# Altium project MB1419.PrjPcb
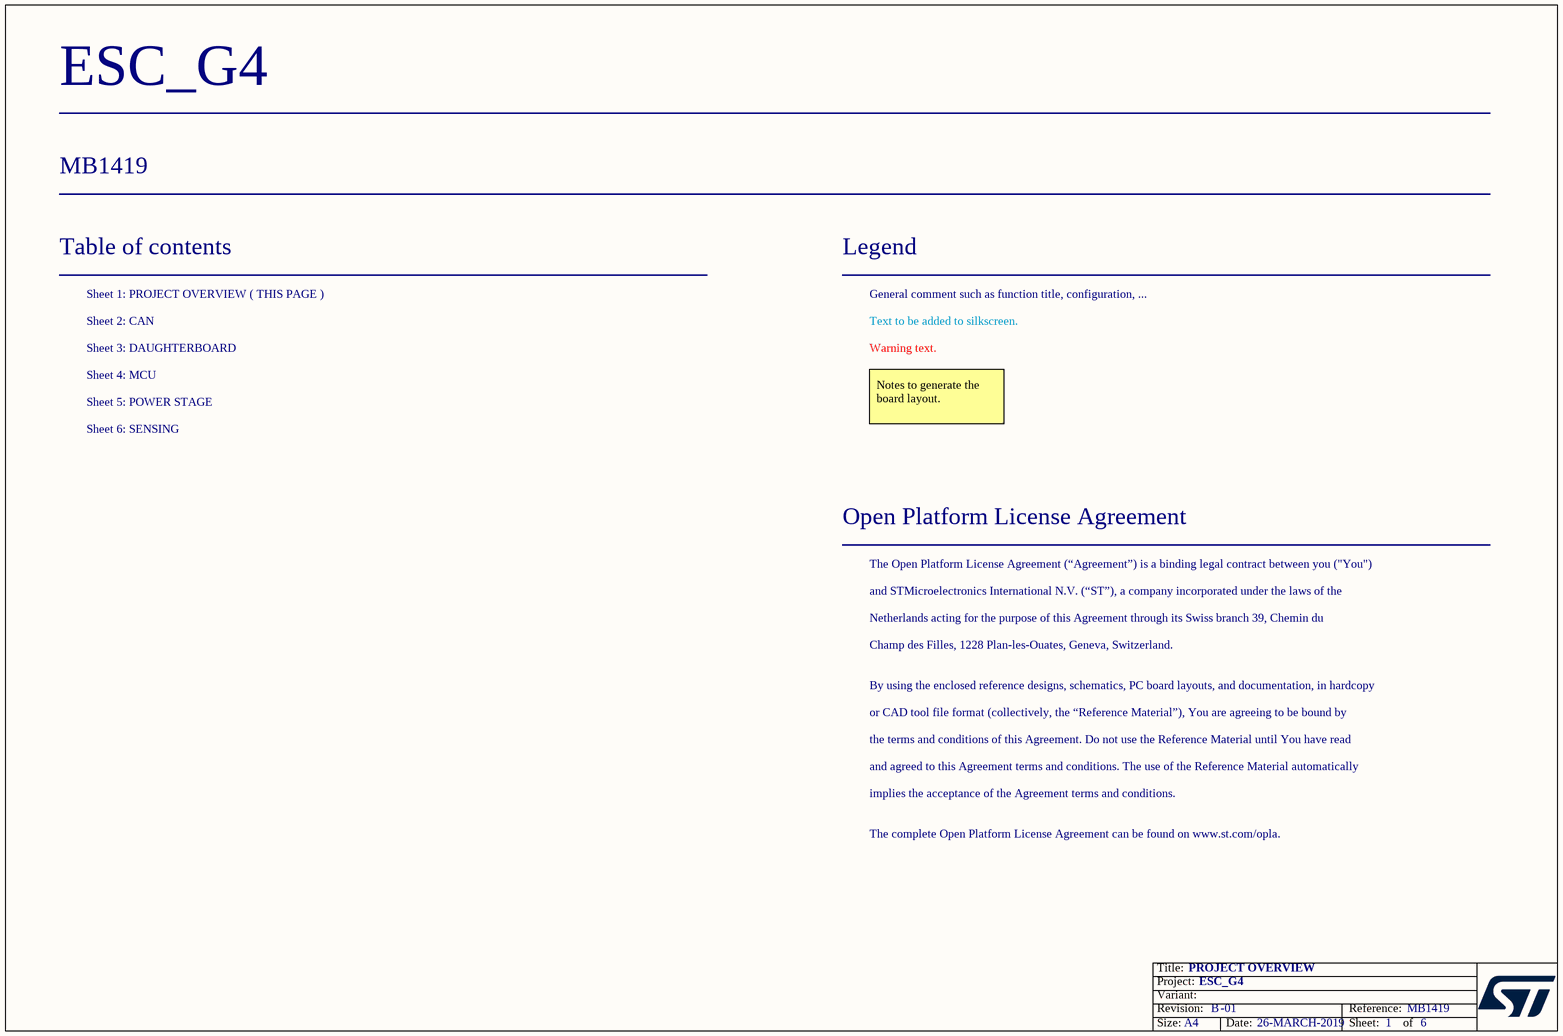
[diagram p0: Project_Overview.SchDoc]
Board_Assembly_Revision: 01; Board_Document_Date: 26-MARCH-2019; Board_Name: ESC_G4; Board_PCB_Revision: B; Board_Reference: MB1419
6 sheets, 211 parts. Net scope: global (net labels, ports and power ports of the same name join across sheets).
Board file: MB1419.PcbDoc
Sheets:
  Project_Overview.SchDoc
  CAN.SchDoc
  DAUGHTERBOARD.SchDoc
  MCU.SchDoc
  POWER STAGE.SchDoc
  SENSING.SchDoc

## Sheet Project_Overview.SchDoc: PROJECT OVERVIEW
size A4; Date: Not used; ApprovedBy: Not used; CheckedBy: Not used; Author: Not used; CompanyName: STMicroelectronics; DrawnBy: Not used; Engineer: Not used; Organization: Not used; Address1: Not used; Address2: Not used; Address3: Not used; Address4: Not used; DocumentNumber: 1; Revision: Not used; SheetNumber: 1; SheetTotal: 6

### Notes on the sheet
- Table of contents
- Sheet 1: PROJECT OVERVIEW ( THIS PAGE )
- Legend
- General comment such as function title, configuration, ...
- Sheet 2: CAN
- Sheet 3: DAUGHTERBOARD
- Sheet 4: MCU
- Text to be added to silkscreen.
- Warning text.
- Sheet 6: SENSING
- Sheet 5: POWER STAGE
- Notes to generate the board layout.
- Open Platform License Agreement
- The Open Platform License Agreement (“Agreement”) is a binding legal contract between you ("You")
- and STMicroelectronics International N.V. (“ST”), a company incorporated under the laws of the
- Netherlands acting for the purpose of this Agreement through its Swiss branch 39, Chemin du
- Champ des Filles, 1228 Plan-les-Ouates, Geneva, Switzerland.
- By using the enclosed reference designs, schematics, PC board layouts, and documentation, in hardcopy
- or CAD tool file format (collectively, the “Reference Material”), You are agreeing to be bound by
- the terms and conditions of this Agreement. Do not use the Reference Material until You have read
- and agreed to this Agreement terms and conditions. The use of the Reference Material automatically
- implies the acceptance of the Agreement terms and conditions.
- The complete Open Platform License Agreement can be found on www.st.com/opla.

## Sheet CAN.SchDoc: CAN
size A4; DocumentNumber: 2; SheetNumber: 2; SheetTotal: 6
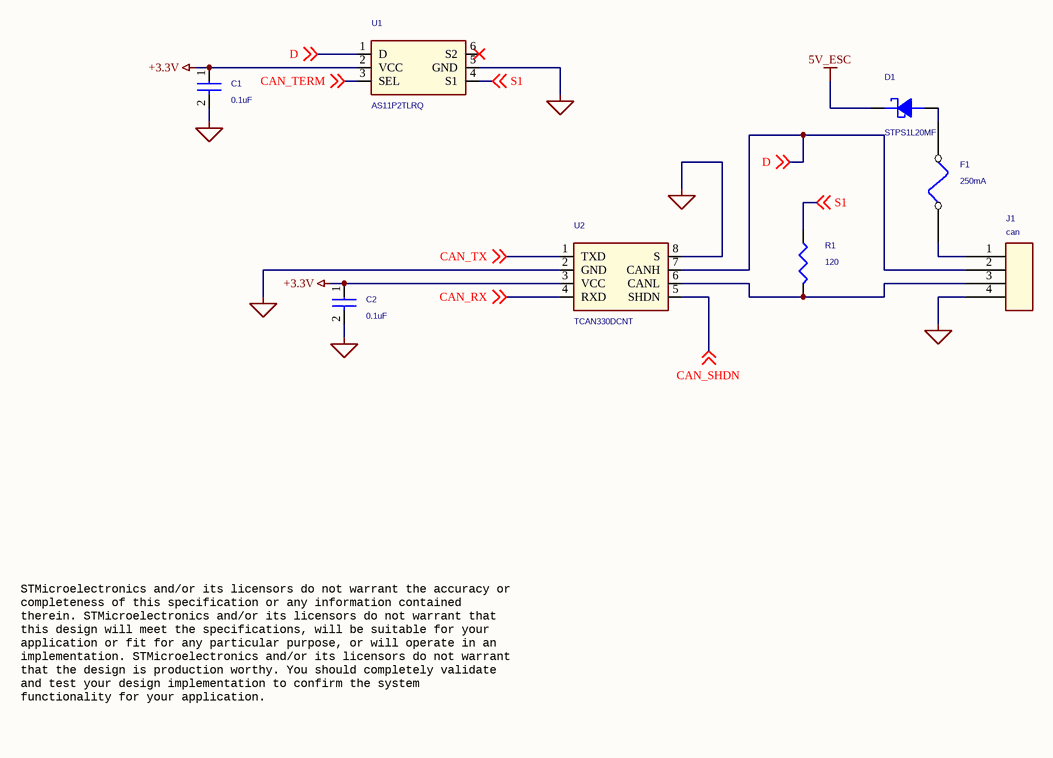
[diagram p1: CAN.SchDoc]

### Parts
C1  0.1uF  [C_0402]
C2  0.1uF  [C_0402]
D1  STPS1L20MF  [do216-aa-flat]
F1  250mA  [f_0402]
J1  can  [SOLDER_PAD_4PIN_SMD]
R1  120  [R_0402]
U1  AS11P2TLRQ  [son6p40_120x100x55l35x20]
U2  TCAN330DCNT  [sot23-8p65_280x145l45x30n]

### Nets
5V_ESC: D1.C
+3.3V: C1.1 C2.1 U1.2(VCC) U2.3(VCC)
GND_SIGNAL: C1.2 C2.2 J1.4 U1.5(GND) U2.2(GND) U2.8(S)  [project net GND]
CAN_RX: U2.4(RXD) ; off-sheet CAN_RX
CAN_SHDN: U2.5(SHDN) ; off-sheet CAN_SHDN
CAN_TERM: U1.3(SEL) ; off-sheet CAN_TERM
CAN_TX: U2.1(TXD) ; off-sheet CAN_TX
D: J1.2 U1.1(D) U2.7(CANH) ; off-sheet D
S1: R1.1 U1.4(S1) ; off-sheet S1
NetD1_A: D1.A F1.2
NetF1_1: F1.1 J1.1
NetJ1_3: J1.3 R1.2 U2.6(CANL)

Not connected (* = marked no-connect by the designer): U1 6(S2)*

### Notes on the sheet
- STMicroelectronics and/or its licensors do not warrant the accuracy or
  completeness of this specification or any information contained
  therein. STMicroelectronics and/or its licensors do not warrant that
  this design will meet the specifications, will be suitable for your
  application or fit for any particular purpose, or will operate in an
  implementation. STMicroelectronics and/or its licensors do not warrant
  that the design is production worthy. You should completely validate
  and test your design implementation to confirm the system
  functionality for your application.

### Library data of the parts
C1 C2 = CAP_Dup1: CAP CER 0.1UF 16V X7R 0402; PART_NUMBER: CAP-00000053; Manufacturer: Wurth Electronics Inc.; Manufacturer PN: 885012205037; Dielectric Type: Capacitors; Tolerance: 10%; CLASS: DISCRETE
D1 = DIODE_SCHOTTKY_0: DIODE SCHOTTKY 20V 1A STMITEFLAT; Manufacturer: STMicroelectronics; PART_NUMBER: TMP-380; CLASS: DISCRETE; Rated Voltage: 430mV @ 1A
F1 = FUSE: FUSE BOARD MNT 250MA 32VDC 0402; Manufacturer Code: 0435.250KRS; Manufacturer: Littelfuse Inc.; PART_NUMBER: TMP-439; RS/Distrelec/Other Code: MOUSER: 576-0435.250KRS; CLASS: DISCRETE
J1 = CON4: SOLDER PADS
R1 = RES: RES SMD 120 OHM 1% 1/16W 0402; PART_NUMBER: TMP-441; Manufacturer: Yageo; Manufacturer PN: RC0402FR-07120RL; Temperature Coefficient: 100ppm/C; Rated Power: 0.063W, 1/16W; CLASS: DISCRETE
U1 = AS11P2TLR: IC ANLG SWITCH SGL SPDT 6QFN; Manufacturer: STMicroelectronics; PART_NUMBER: TMP-378
U2 = TCAN330: IC TXRX CAN 3.3V SOT-23; PART_NUMBER: TMP-379; Manufacturer: Texas Instruments; Supply Voltage: 3 V ~ 3.6 V

## Sheet DAUGHTERBOARD.SchDoc: DAUGHTERBOARD
size A3; DocumentNumber: 3; SheetNumber: 3; SheetTotal: 6
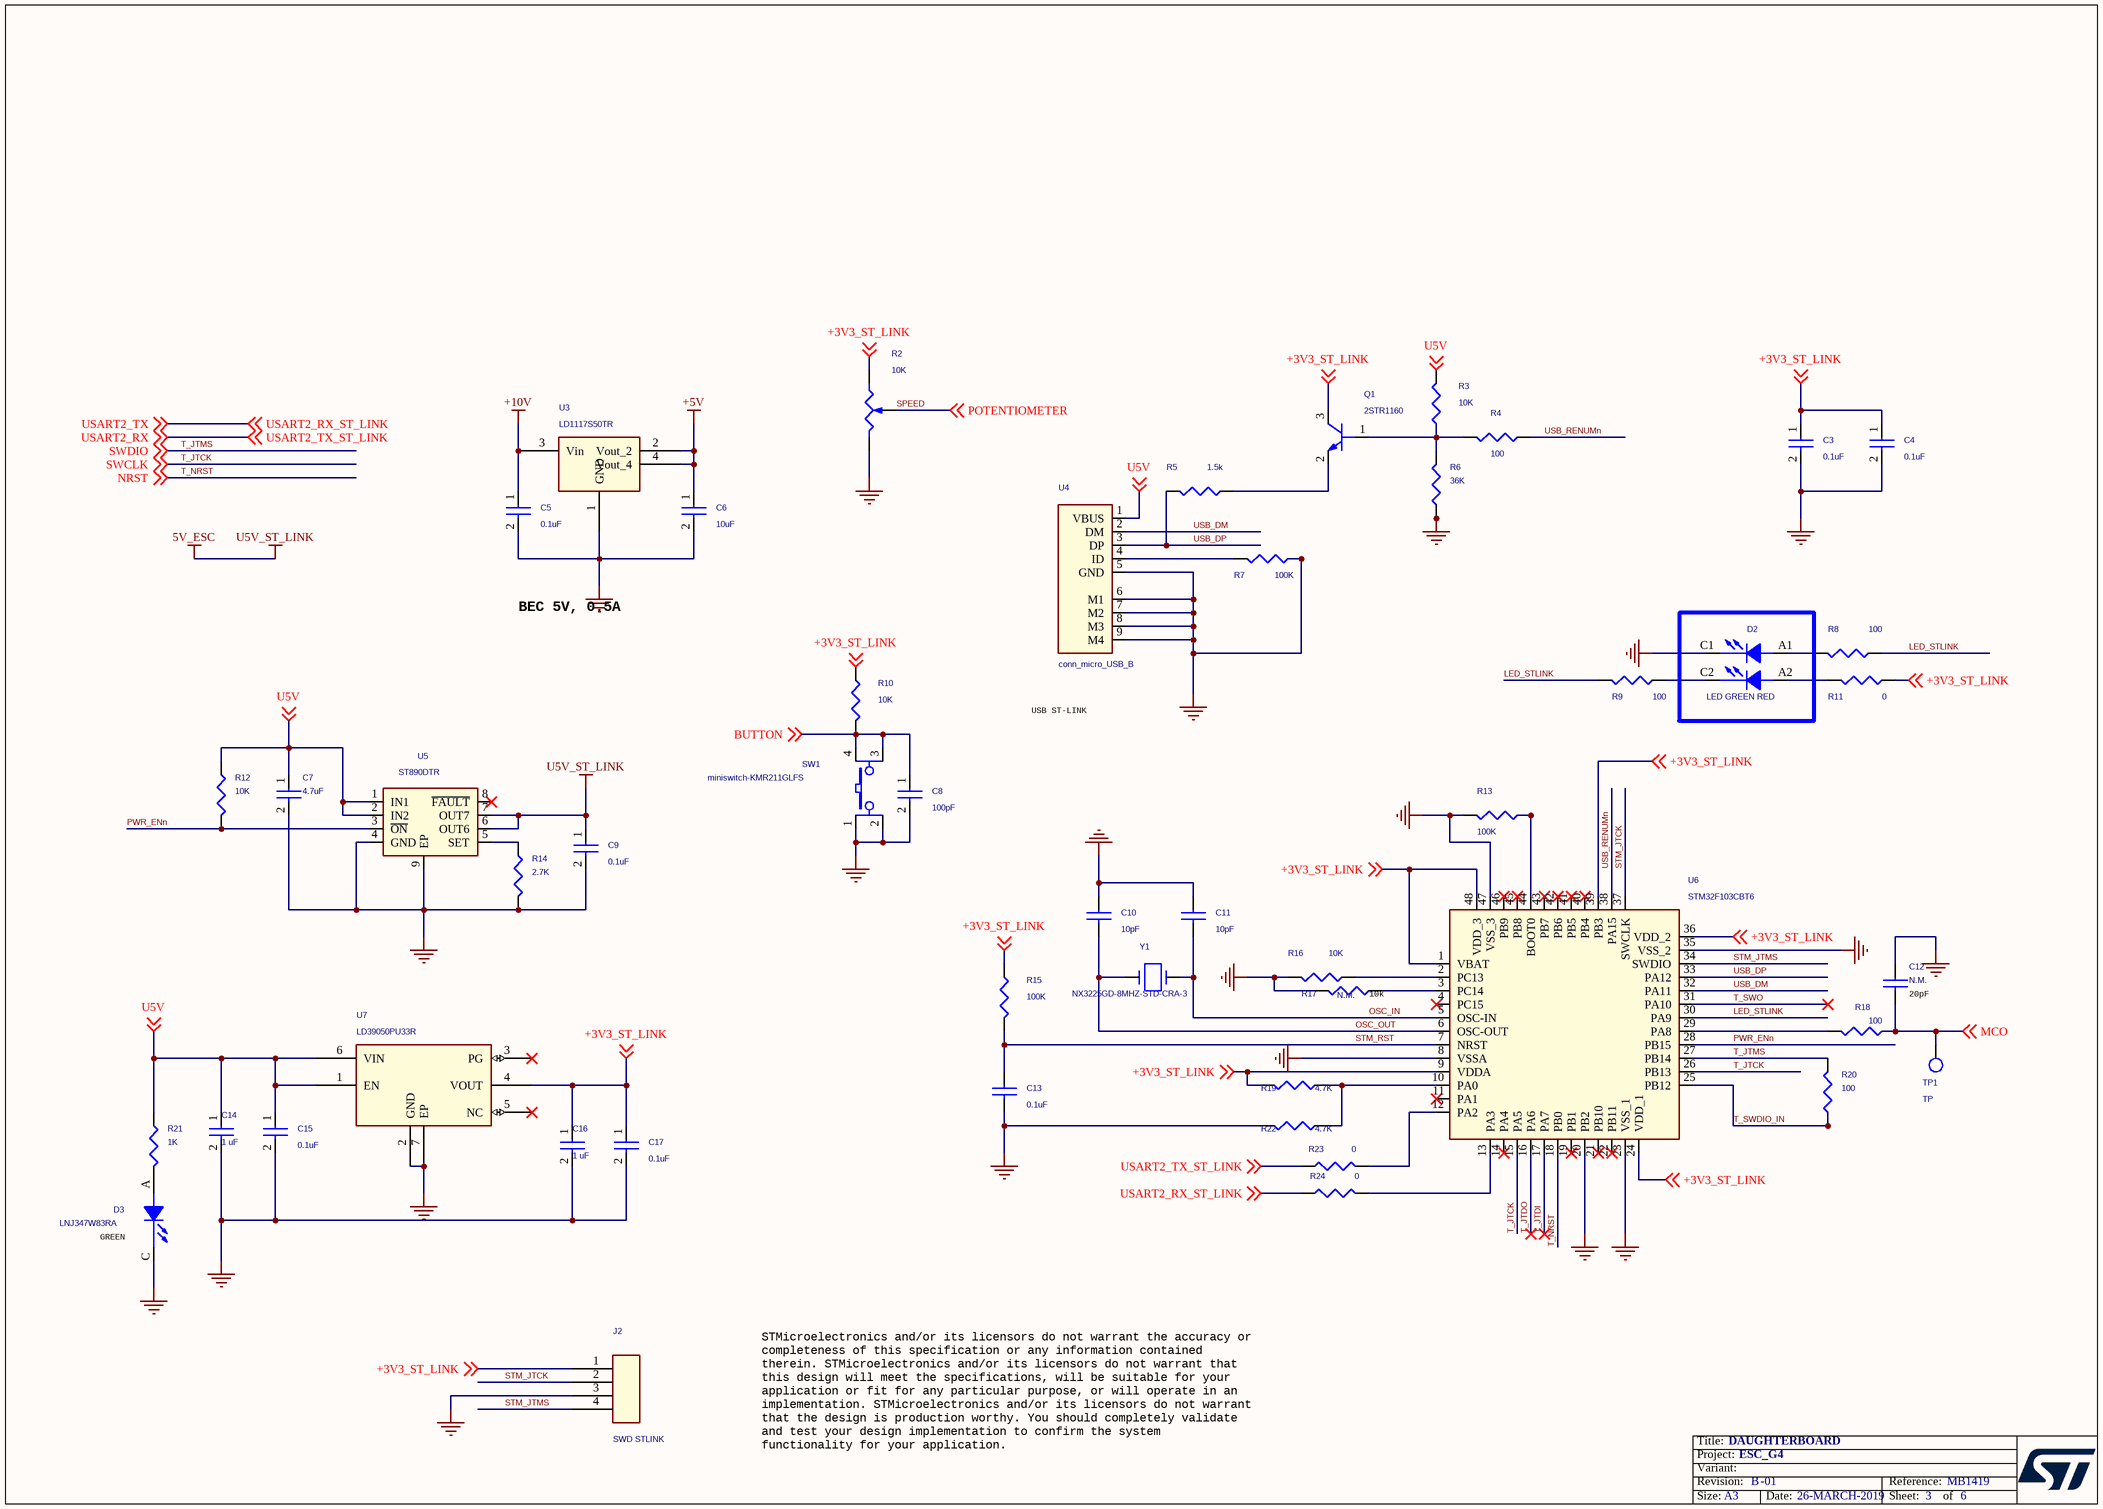
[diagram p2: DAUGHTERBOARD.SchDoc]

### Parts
C3  0.1uF  [C_0402]
C4  0.1uF  [C_0402]
C5  0.1uF  [C_0402]
C6  10uF  [C_0805]
C7  4.7uF  [C_0805]
C8  100pF  [C_0402]
C9  0.1uF  [C_0402]
C10  10pF  [C_0402]
C11  10pF  [C_0402]
C12  N.M.  [C_0402]
C13  0.1uF  [C_0402]
C14  1 uF  [C_0603]
C15  0.1uF  [C_0603]
C16  1 uF  [C_0603]
C17  0.1uF  [C_0402]
D2  LED GREEN RED  [Led_bicolor_3528-PLCC-4]
D3  LNJ347W83RA  [D_0402_Led_green]
J2  SWD STLINK  [strip4_100m_v]
Q1  2STR1160  [sot23-3p97_255x140l40x40n]
R2  10K  [trimmer-3386P_T]
R3  10K  [R_0402]
R4  100  [R_0402]
R5  1.5k  [R_0402]
R6  36K  [R_0402]
R7  100K  [R_0402]
R8  100  [R_0402]
R9  100  [R_0402]
R10  10K  [R_0402]
R11  0  [R_0402]
R12  10K  [R_0402]
R13  100K  [R_0402]
R14  2.7K  [R_0402]
R15  100K  [R_0402]
R16  10K  [R_0402]
R17  N.M.  [R_0402]
R18  100  [R_0402]
R19  4.7K  [R_0402]
R20  100  [R_0402]
R21  1K  [R_0402]
R22  4.7K  [R_0402]
R23  0  [JUMPER_0603_DROP]
R24  0  [JUMPER_0603_DROP]
SW1  miniswitch-KMR211GLFS  [switch_SMT_4_2x2_8mm]
TP1  TP  [test_point_100_smd]
U3  LD1117S50TR  [sot223-4p230_700x190l65x72]
U4  conn_micro_USB_B  [conn_micro_USB_B_SMD]
U5  ST890DTR  [son9p65_300x300x90l30x30t240-1]
U6  STM32F103CBT6  [qfp48p50_900x900x160l60x22n]
U7  LD39050PU33R  [son7p95_300x300x100l40x34t23-1]
Y1  NX3225GD-8MHZ-STD-CRA-3  [xtaldfn2_320x250x100l130x230]

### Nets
5V_ESC: C9.1 U5.6(OUT6) U5.7(OUT7)  [also labelled U5V_ST_LINK]
+5V: C6.1 U3.2(Vout_2) U3.4(Vout_4)
+10V: C5.1 U3.3(Vin)
GND: C3.2 C4.2 C5.2 C6.2 C7.2 C8.2 C9.2 C10.1 C11.1 C12.1 C13.2 C14.2 C15.2 C16.2 C17.2 D2.C1(CATHODE1) D3.C(CATHODE) J2.3 R2.1(A) R6.1 R7.1 R13.2 R14.2 R16.2 R17.2 R22.2 SW1.1 SW1.2 U3.1(GND) U4.5(GND) U4.6(M1) U4.7(M2) U4.8(M3) U4.9(M4) U5.4(GND) U5.9(EP) U6.8(VSSA) U6.20(PB2) U6.23(VSS_1) U6.35(VSS_2) U6.47(VSS_3) U7.2(GND) U7.7(EP)
+3V3_ST_LINK: C3.1 C4.1 C16.1 C17.1 J2.1 Q1.3(C) R2.3(B) R10.1 R11.1 R15.1 R19.2 U6.1(VBAT) U6.9(VDDA) U6.24(VDD_1) U6.36(VDD_2) U6.39(PB3) U6.48(VDD_3) U7.4(VOUT) ; off-sheet +3V3_ST_LINK
BUTTON: C8.1 R10.2 SW1.3 SW1.4 ; off-sheet BUTTON
LED_STLINK: R8.1 R9.2 U6.30(PA9)
MCO: C12.2 R18.1 TP1.1 ; off-sheet MCO
OSC_IN: C11.2 U6.5(OSC-IN) Y1.1
OSC_OUT: C10.2 U6.6(OSC-OUT) Y1.2
PWR_ENn: R12.2 U5.3(~{ON}) U6.28(PB15)
SPEED: R2.2(WIPER) ; off-sheet POTENTIOMETER  [also labelled POTENTIOMETER]
STM_JTCK: J2.2 U6.37(SWCLK)
STM_JTMS: J2.4 U6.34(SWDIO)
STM_RST: C13.1 R15.2 U6.7(NRST)
T_JTCK: U6.15(PA5) U6.26(PB13) ; off-sheet SWCLK  [also labelled SWCLK]
T_JTDI: U6.17(PA7)
T_JTDO: U6.16(PA6)
T_JTMS: R20.2 U6.27(PB14) ; off-sheet SWDIO  [also labelled SWDIO]
T_NRST: U6.18(PB0) ; off-sheet NRST  [also labelled NRST]
T_SWDIO_IN: R20.1 U6.25(PB12)
T_SWO: U6.31(PA10)
U5V: C7.1 C14.1 C15.1 R3.2 R12.1 R21.1 U4.1(VBUS) U5.1(IN1) U5.2(IN2) U7.1(EN) U7.6(VIN) ; off-sheet U5V
USART2_RX: R23.1 ; off-sheet USART2_TX_ST_LINK, off-sheet USART2_RX  [also labelled USART2_TX_ST_LINK]
USART2_RX_ST_LINK: R24.1 ; off-sheet USART2_RX_ST_LINK, off-sheet USART2_TX  [also labelled USART2_TX]
USB_DM: U4.2(DM) U6.32(PA11)
USB_DP: R5.2 U4.3(DP) U6.33(PA12)
USB_RENUMn: R4.1 U6.38(PA15)
NetD2_A1: D2.A1(ANODE1) R8.2
NetD2_A2: D2.A2(ANODE2) R11.2
NetD2_C2: D2.C2(CATHODE2) R9.1
NetD3_A: D3.A(ANODE) R21.2
NetQ1_1: Q1.1(B) R3.1 R4.2 R6.2
NetQ1_2: Q1.2(E) R5.1
NetR7_2: R7.2 U4.4(ID)
NetR13_1: R13.1 U6.44(BOOT0)
NetR14_1: R14.1 U5.5(SET)
NetR16_1: R16.1 U6.2(PC13)
NetR17_1: R17.1 U6.3(PC14)
NetR18_2: R18.2 U6.29(PA8)
NetR19_1: R19.1 R22.1 U6.10(PA0)
NetR23_2: R23.2 U6.12(PA2)
NetR24_2: R24.2 U6.13(PA3)

Not connected (* = marked no-connect by the designer): U5 8(~{FAULT})*; U6 4(PC15)* 11(PA1)* 14(PA4)* 19(PB1)* 21(PB10)* 22(PB11)* 40(PB4)* 41(PB5)* 42(PB6)* 43(PB7)* 45(PB8)* 46(PB9)*; U7 3(PG)* 5(NC)*

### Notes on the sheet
- BEC 5V, 0.5A
- USB ST-LINK
- (near R17) 10k
- (near C12) 20pF
- (near D3) GREEN
- STMicroelectronics and/or its licensors do not warrant the accuracy or
  completeness of this specification or any information contained
  therein. STMicroelectronics and/or its licensors do not warrant that
  this design will meet the specifications, will be suitable for your
  application or fit for any particular purpose, or will operate in an
  implementation. STMicroelectronics and/or its licensors do not warrant
  that the design is production worthy. You should completely validate
  and test your design implementation to confirm the system
  functionality for your application.

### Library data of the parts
C3-C5 C9 = CAP_Dup1: CAP CER 0.1UF 16V X7R 0402; Manufacturer PN: 885012205037; Manufacturer: Wurth Electronics Inc.; PART_NUMBER: CAP-00000053; CLASS: DISCRETE; Tolerance: 10%; Dielectric Type: Capacitors
C6 = CAP_Dup1: CAP CER 10UF 16V X5R 0805; Manufacturer PN: 885012107014; Manufacturer: Wurth Electronics Inc.; PART_NUMBER: TMP-409; CLASS: DISCRETE; Tolerance: 20%; Dielectric Type: Capacitors
C7 = CAP_Dup1: CAP CER 4.7UF 16V X5R 0805; PART_NUMBER: TMP-410; Manufacturer: Wurth Electronics Inc.; Manufacturer PN: 885012107013; Dielectric Type: Capacitors; Tolerance: 20%; CLASS: DISCRETE
C8 = CAP_Dup1: CAP CER 100PF 10V C0G/NP0 0402; PART_NUMBER: TMP-412; Manufacturer: Wurth Electronics Inc.; Manufacturer PN: 885012005013; Dielectric Type: Capacitors; Temperature Coefficient: C0G, NP0; Tolerance: 5%; CLASS: DISCRETE
C10 C11 = CAP_7: CAP CER 10PF 10V C0G/NP0 0402; PART_NUMBER: TMP-395; Manufacturer: Wurth Electronics Inc.; Manufacturer PN: 885012005007; Dielectric Type: Capacitors; Temperature Coefficient: C0G, NP0; Tolerance: 5%; CLASS: DISCRETE
C12 = CAP_6: CAP CER 0402-NOT MOUNTED; PART_NUMBER: TMP-408; CLASS: DISCRETE
C13 = CAP_8: CAP CER 0.1UF 16V X7R 0402; PART_NUMBER: CAP-00000053; Manufacturer: Wurth Electronics Inc.; Manufacturer PN: 885012205037; Dielectric Type: Capacitors; Tolerance: 10%; CLASS: DISCRETE
C14 C16 = CAP_Dup1: CAP CER 1UF 16V X5R 0603; PART_NUMBER: TMP-302; Manufacturer: Yageo; Manufacturer PN: CC0603KRX5R7BB105; Dielectric Type: Capacitors; Tolerance: 10%; CLASS: DISCRETE
C15 = CAP_Dup1: CAP CER 0.1UF 16V X7R 0603; Manufacturer PN: 885012206046; Manufacturer: Wurth Electronics Inc.; PART_NUMBER: CAP-00000052; CLASS: DISCRETE; Tolerance: 10%; Dielectric Type: Capacitors
C17 = CAP_Dup1: as C1 on sheet CAN
D2 = LED_BICOLOR: LED GREEN/RED CLEAR 4PLCC SMD; PART_NUMBER: TMP-705; Manufacturer: Wurth Electronics Inc.; Manufacturer PN: 150141RV73100; CLASS: DISCRETE
D3 = LED: LED GREEN 0402 SMD; Manufacturer: Panasonic Electronic Components; PART_NUMBER: TMP-187; CLASS: DISCRETE
J2 = CON4: SOLDER PADS
Q1 = BJT_NPN_BEC: TRANS NPN 60V 1A SOT-23; PART_NUMBER: TMP-433; Manufacturer: STMicroelectronics; CLASS: DISCRETE
R2 = POT: TRIMMER 10K OHM 0.5W PC PIN; PART_NUMBER: TMP-491; Manufacturer: Bourns Inc.; Manufacturer PN: 3386P-1-103TLF; Temperature Coefficient: 100ppm/C; Tolerance: 10%; Rated Power: 0.5W, 1/2W; CLASS: DISCRETE
R3 R12 = RES: RES SMD 10K OHM 1% 1/16W 0402; Manufacturer PN: RC0402FR-0710KL; Manufacturer: Yageo; PART_NUMBER: TMP-396; CLASS: DISCRETE; Rated Power: 0.063W, 1/16W; Temperature Coefficient: 100ppm/C
R4 R8 R20 = RES: RES SMD 100 OHM 1% 1/16W 0402; PART_NUMBER: TMP-406; Manufacturer: TE Connectivity Passive Product; Manufacturer PN: CRG0402F100R; Temperature Coefficient: 100ppm/C; Rated Power: 0.063W, 1/16W; CLASS: DISCRETE
R5 = RES: RES SMD 1.5K OHM 1% 1/16W 0402; PART_NUMBER: TMP-393; Manufacturer: Yageo; Manufacturer PN: RC0402FR-071K5L; Temperature Coefficient: 100ppm/C; Rated Power: 0.063W, 1/16W; CLASS: DISCRETE
R6 = RES: RES SMD 36K OHM 1% 1/16W 0402; Manufacturer PN: RC0402FR-0736KL; Manufacturer: Yageo; PART_NUMBER: TMP-436; CLASS: DISCRETE; Rated Power: 0.063W, 1/16W; Temperature Coefficient: 100ppm/C
R7 R13 = RES: RES SMD 100K OHM 1% 1/16W 0402; Manufacturer PN: CRG0402F100K; Manufacturer: TE Connectivity Passive Product; PART_NUMBER: TMP-405; CLASS: DISCRETE; Rated Power: 0.063W, 1/16W; Temperature Coefficient: 100ppm/C
R9 R18 = RES: RES SMD 100 OHM 1% 1/16W 0402; Manufacturer PN: CRG0402F100R; Manufacturer: TE Connectivity Passive Product; PART_NUMBER: TMP-406; CLASS: DISCRETE; Rated Power: 0.063W, 1/16W; Temperature Coefficient: 100ppm/C
R10 R16 = RES: RES SMD 10K OHM 1% 1/16W 0402; PART_NUMBER: TMP-396; Manufacturer: Yageo; Manufacturer PN: RC0402FR-0710KL; Temperature Coefficient: 100ppm/C; Rated Power: 0.063W, 1/16W; CLASS: DISCRETE
R11 = RES: RES SMD 0 OHM JUMPER 1/16W 0402; Manufacturer PN: CRCW04020000Z0ED; Manufacturer: Vishay Dale; PART_NUMBER: RES-00000073; CLASS: DISCRETE; Rated Power: 0.063W, 1/16W
R14 = RES: RES SMD 2.7K OHM 1% 1/16W 0402; PART_NUMBER: TMP-411; Manufacturer: Yageo; Manufacturer PN: RC0402FR-072K7L; Temperature Coefficient: 100ppm/C; Rated Power: 0.063W, 1/16W; CLASS: DISCRETE
R15 = RES: RES SMD 100K OHM 1% 1/16W 0402; PART_NUMBER: TMP-405; Manufacturer: TE Connectivity Passive Product; Manufacturer PN: CRG0402F100K; Temperature Coefficient: 100ppm/C; Rated Power: 0.063W, 1/16W; CLASS: DISCRETE
R17 = RES: RES SMD 0402 - NOT MOUNTED; PART_NUMBER: TMP-404; CLASS: DISCRETE
R19 R22 = RES: RES SMD 4.7K OHM 1% 1/16W 0402; PART_NUMBER: TMP-403; Manufacturer: TE Connectivity Passive Product; Manufacturer PN: CRG0402F4K7; Temperature Coefficient: 100ppm/C; Rated Power: 0.063W, 1/16W; CLASS: DISCRETE
R21 = RES: RES SMD 1K OHM 1% 1/16W 0402; PART_NUMBER: TMP-352; Manufacturer: Yageo; Manufacturer PN: RC0402FR-071KL; Temperature Coefficient: 100ppm/C; Rated Power: 0.063W, 1/16W; CLASS: DISCRETE; ALT_SYMBOLS: r_0402_hd
R23 = RES: RES SMD 0 OHM JUMPER 1/10W 0603; Manufacturer PN: ERJ-3GEY0R00V; Manufacturer: Panasonic Electronic Components; PART_NUMBER: RES-00000056; CLASS: DISCRETE; Rated Power: 0.1W, 1/10W
R24 = RES: RES SMD 0 OHM JUMPER 1/10W 0603; PART_NUMBER: RES-00000056; Manufacturer: Panasonic Electronic Components; Manufacturer PN: ERJ-3GEY0R00V; Rated Power: 0.1W, 1/10W; CLASS: DISCRETE
SW1 = PUSHBUTTON-SPST-2: SWITCH TACTILE SPST-NO 0.05A 32V; Manufacturer: C&K; PART_NUMBER: TMP-285; CLASS: DISCRETE
TP1 = TESTPOINT: TEST POINT 1MM  SMD PADSTASCK; PART_NUMBER: TMP-386; CLASS: IO
U3 = LD1117SxxxTR_0: IC REG LINEAR 5V 800MA SOT223; Manufacturer: STMicroelectronics; PART_NUMBER: TMP-381
U4 = USB_MICRO: CONN RCPT 5POS MICRO USB R/A; Manufacturer PN: 0473460001; Manufacturer: Molex, LLC; PART_NUMBER: TMP-434; CLASS: IO
U5 = ST890DTR: IC PWR SWITCH 1.2A HISIDE 8-DFN; Manufacturer: STMicroelectronics; PART_NUMBER: TMP-432; Supply Voltage: Not Required
U6 = STM32F103CBT6: IC MCU 32BIT 128KB FLASH 48LQFP; PART_NUMBER: TMP-399; Manufacturer: STMicroelectronics; Supply Voltage: 2 V ~ 3.6 V
U7 = LD39050PU33R: IC REG LINEAR 3.3V 500MA 6DFN; PART_NUMBER: TMP-358; Manufacturer: STMicroelectronics
Y1 = crystal: CRYSTAL 8.0000MHZ 8PF SMD; Manufacturer: NDK America, Inc.; PART_NUMBER: TMP-435; CLASS: DISCRETE; Frequency Tolerance: 50ppm; Frequency Stability: 150ppm

## Sheet MCU.SchDoc: MVU
size A3; DocumentNumber: 4; SheetNumber: 4; SheetTotal: 6
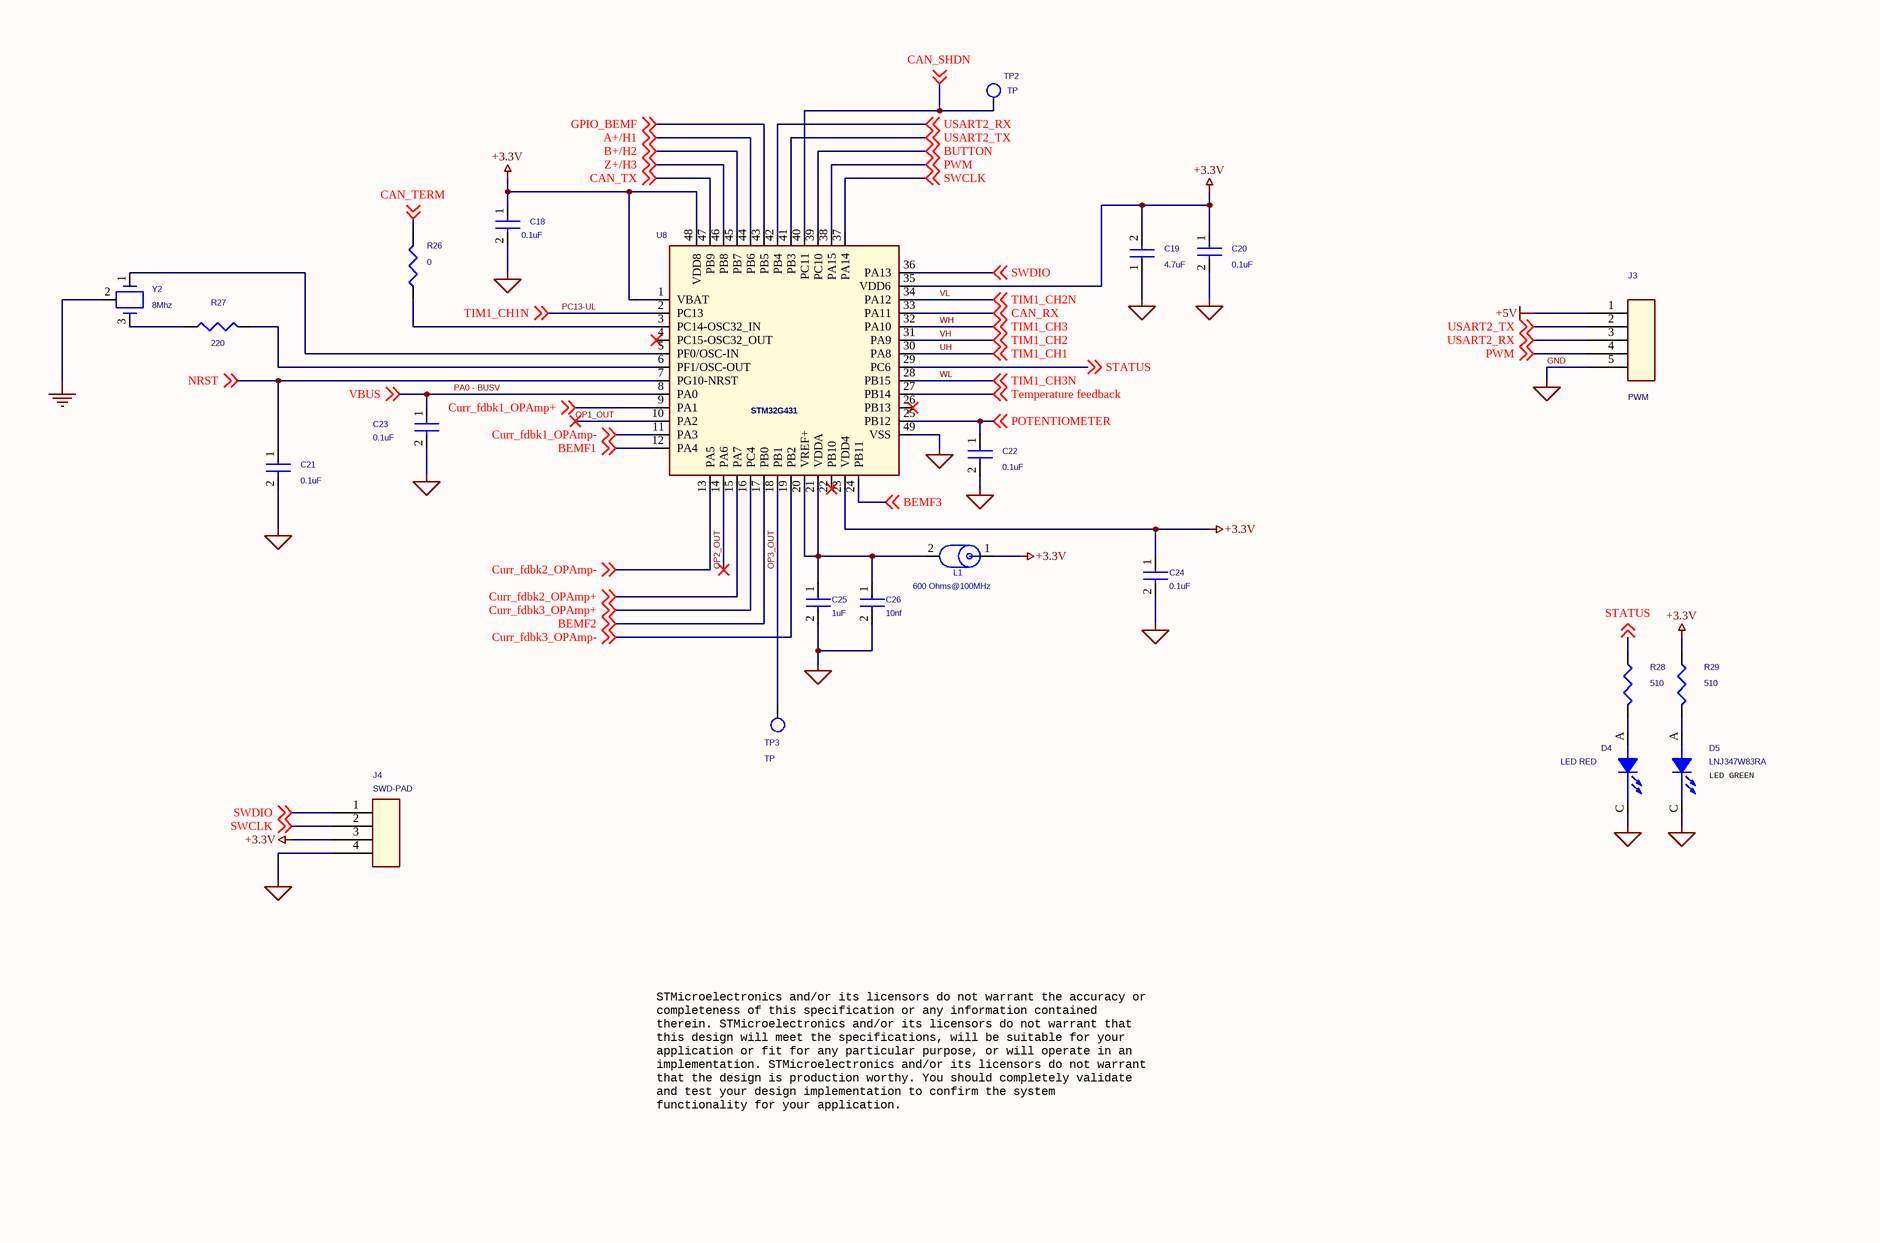
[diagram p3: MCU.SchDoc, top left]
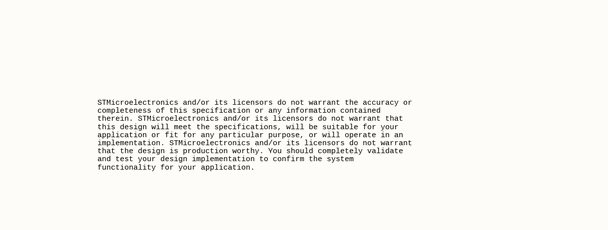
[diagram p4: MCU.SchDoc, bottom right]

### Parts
C18  0.1uF  [C_0402]
C19  4.7uF  [C_0603]
C20  0.1uF  [C_0402]
C21  0.1uF  [C_0402]
C22  0.1uF  [C_0402]
C23  0.1uF  [C_0402]
C24  0.1uF  [C_0402]
C25  1uF  [C_0402]
C26  10nf  [C_0402]
D4  LED RED  [D_0402_Led_red]
D5  LNJ347W83RA  [D_0402_Led_green]
J3  PWM  [SOLDER_PAD_5PIN_SMD]
J4  SWD-PAD  [SOLDER_PAD_4PIN_rect_SMD]
L1  600 Ohms@100MHz  [L_0402]
R26  0  [R_0402]
R27  220  [R_0402]
R28  510  [R_0402]
R29  510  [R_0402]
TP2  TP  [test_point_100_smd]
TP3  TP  [test_point_100_smd]
U8  STM32G431  [qfn49p50_700x700x60l40x25t560n]
Y2  8Mhz  [murata_cstce8m00g15c99-r0]

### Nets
+3.3V: C18.1 C19.2 C20.1 C24.1 J4.3 L1.1 R29.1 U8.1(VBAT) U8.23(VDD4) U8.35(VDD6) U8.48(VDD8)
+5V: J3.1
GND: C18.2 C19.1 C20.2 C21.2 C22.2 C23.2 C24.2 C25.2 C26.2 D4.C(CATHODE) D5.C(CATHODE) J3.5 J4.4 U8.49(VSS) Y2.2  [also labelled GND_SIGNAL]
A+/H1: U8.44(PB6) ; off-sheet A+/H1
B+/H2: U8.45(PB7) ; off-sheet B+/H2
BEMF1: U8.12(PA4) ; off-sheet BEMF1
BEMF2: U8.17(PB0) ; off-sheet BEMF2
BEMF3: U8.24(PB11) ; off-sheet BEMF3
BUTTON: U8.39(PC10) ; off-sheet BUTTON
CAN_RX: U8.33(PA11) ; off-sheet CAN_RX
CAN_SHDN: TP2.1 U8.40(PC11) ; off-sheet CAN_SHDN
CAN_TERM: R26.2 ; off-sheet CAN_TERM
CAN_TX: U8.47(PB9) ; off-sheet CAN_TX
Curr_fdbk1_OPAmp+: U8.9(PA1) ; off-sheet Curr_fdbk1_OPAmp+
Curr_fdbk1_OPAmp-: U8.11(PA3) ; off-sheet Curr_fdbk1_OPAmp-
Curr_fdbk2_OPAmp+: U8.15(PA7) ; off-sheet Curr_fdbk2_OPAmp+
Curr_fdbk2_OPAmp-: U8.13(PA5) ; off-sheet Curr_fdbk2_OPAmp-
Curr_fdbk3_OPAmp+: U8.16(PC4) ; off-sheet Curr_fdbk3_OPAmp+
Curr_fdbk3_OPAmp-: U8.19(PB2) ; off-sheet Curr_fdbk3_OPAmp-
GPIO_BEMF: U8.43(PB5) ; off-sheet GPIO_BEMF
NRST: C21.1 U8.7(PG10-NRST) ; off-sheet NRST  [project net T_NRST]
OP1_OUT: U8.10(PA2)
OP2_OUT: U8.14(PA6)
OP3_OUT: TP3.1 U8.18(PB1)
PA0 - BUSV: C23.1 U8.8(PA0) ; off-sheet VBUS  [also labelled VBUS]
PC13-UL: U8.2(PC13) ; off-sheet TIM1_CH1N  [also labelled TIM1_CH1N]
POTENTIOMETER: C22.1 U8.25(PB12) ; off-sheet POTENTIOMETER  [project net SPEED]
PWM: J3.4 U8.38(PA15) ; off-sheet PWM
STATUS: R28.1 U8.29(PC6) ; off-sheet STATUS
SWCLK: J4.2 U8.37(PA14) ; off-sheet SWCLK  [project net T_JTCK]
SWDIO: J4.1 U8.36(PA13) ; off-sheet SWDIO  [project net T_JTMS]
Temperature feedback: U8.27(PB14) ; off-sheet Temperature feedback
UH: U8.30(PA8) ; off-sheet TIM1_CH1  [also labelled TIM1_CH1]
USART2_RX: J3.3 U8.42(PB4) ; off-sheet USART2_RX
USART2_TX: J3.2 U8.41(PB3) ; off-sheet USART2_TX  [project net USART2_RX_ST_LINK]
VH: U8.31(PA9) ; off-sheet TIM1_CH2  [also labelled TIM1_CH2]
VL: U8.34(PA12) ; off-sheet TIM1_CH2N  [also labelled TIM1_CH2N]
WH: U8.32(PA10) ; off-sheet TIM1_CH3  [also labelled TIM1_CH3]
WL: U8.28(PB15) ; off-sheet TIM1_CH3N  [also labelled TIM1_CH3N]
Z+/H3: U8.46(PB8) ; off-sheet Z+/H3
NetC25_1: C25.1 C26.1 L1.2 U8.20(VREF+) U8.21(VDDA)
NetD4_A: D4.A(ANODE) R28.2
NetD5_A: D5.A(ANODE) R29.2
NetR26_1: R26.1 U8.3(PC14-OSC32_IN)
NetR27_1: R27.1 Y2.3
NetR27_2: R27.2 U8.6(PF1/OSC-OUT)
NetU8_5: U8.5(PF0/OSC-IN) Y2.1

Not connected (* = marked no-connect by the designer): U8 4(PC15-OSC32_OUT)* 22(PB10)* 26(PB13)*

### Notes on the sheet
- (near D5) LED GREEN
- STMicroelectronics and/or its licensors do not warrant the accuracy or
  completeness of this specification or any information contained
  therein. STMicroelectronics and/or its licensors do not warrant that
  this design will meet the specifications, will be suitable for your
  application or fit for any particular purpose, or will operate in an
  implementation. STMicroelectronics and/or its licensors do not warrant
  that the design is production worthy. You should completely validate
  and test your design implementation to confirm the system
  functionality for your application.

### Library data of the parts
C18 C22 = CAP_Dup1: as C1 on sheet CAN
C19 = CAP_Dup1: CAP CER 4.7UF 10V X5R 0603; Manufacturer PN: 885012106012; Manufacturer: Wurth Electronics Inc.; PART_NUMBER: TMP-414; CLASS: DISCRETE; Tolerance: 20%; Dielectric Type: Capacitors
C20 C21 C23 C24 = CAP_Dup1: as C3 on sheet DAUGHTERBOARD
C25 = CAP_Dup1: CAP CER 1UF 25V X5R 0402; PART_NUMBER: CAP-00000006; Manufacturer: Murata Electronics North America; Manufacturer PN: GRM155R61E105KA12D; Dielectric Type: Capacitors; Tolerance: 10%; CLASS: DISCRETE
C26 = CAP_Dup1: CAP CER 10000PF 16V X7R 0402; PART_NUMBER: TMP-422; Manufacturer: Wurth Electronics Inc.; Manufacturer PN: 885012205031; Dielectric Type: Capacitors; Tolerance: 10%; CLASS: DISCRETE
D4 = LED: DIO, Rectangle with Flat Top, 1.00mm x 0.50mm, VLMS1500-GS08, 20mA, --, --, 0402 (1005 Metric); PART_NUMBER: DIO-00000003; Manufacturer: Vishay Semiconductor Opto Division; CLASS: DISCRETE
D5 = LED: LED GREEN 0402 SMD; PART_NUMBER: TMP-187; Manufacturer: Panasonic Electronic Components; CLASS: DISCRETE
J3 = CON5: SOLDER PADS
J4 = CON4: SOLDER PADS
L1 = IND_FB: FERRITE BEAD 600 OHM 0402 1LN; Manufacturer PN: BLM15BX601SN1D; Manufacturer: Murata Electronics North America; PART_NUMBER: TMP-492; CLASS: DISCRETE
R26 = RES: RES SMD 0 OHM JUMPER 1/16W 0402; PART_NUMBER: RES-00000073; Manufacturer: Vishay Dale; Manufacturer PN: CRCW04020000Z0ED; Rated Power: 0.063W, 1/16W; CLASS: DISCRETE
R27 = RES: RES SMD 220 OHM 1% 1/16W 0402; PART_NUMBER: TMP-437; Manufacturer: Yageo; Manufacturer PN: RC0402FR-07220RL; Temperature Coefficient: 100ppm/C; Rated Power: 0.063W, 1/16W; CLASS: DISCRETE
R28 R29 = RES: RES SMD 510 OHM 1% 1/16W 0402; PART_NUMBER: TMP-438; Manufacturer: Yageo; Manufacturer PN: RC0402FR-07510RL; Temperature Coefficient: 100ppm/C; Rated Power: 0.063W, 1/16W; CLASS: DISCRETE
TP2 TP3 = TESTPOINT: as TP1 on sheet DAUGHTERBOARD
U8 = STM32_LQFP64_6
Y2 = resonator: CER RES 8.0000MHZ 33PF SMD; Manufacturer PN: CSTCE8M00G15C99-R0; Manufacturer: Murata Electronics North America; PART_NUMBER: TMP-382; CLASS: DISCRETE; Frequency Tolerance: 0.1%; Frequency Stability: 0.13%

## Sheet POWER STAGE.SchDoc: POWER STAGE
size A3; DocumentNumber: 5; SheetNumber: 5; SheetTotal: 6
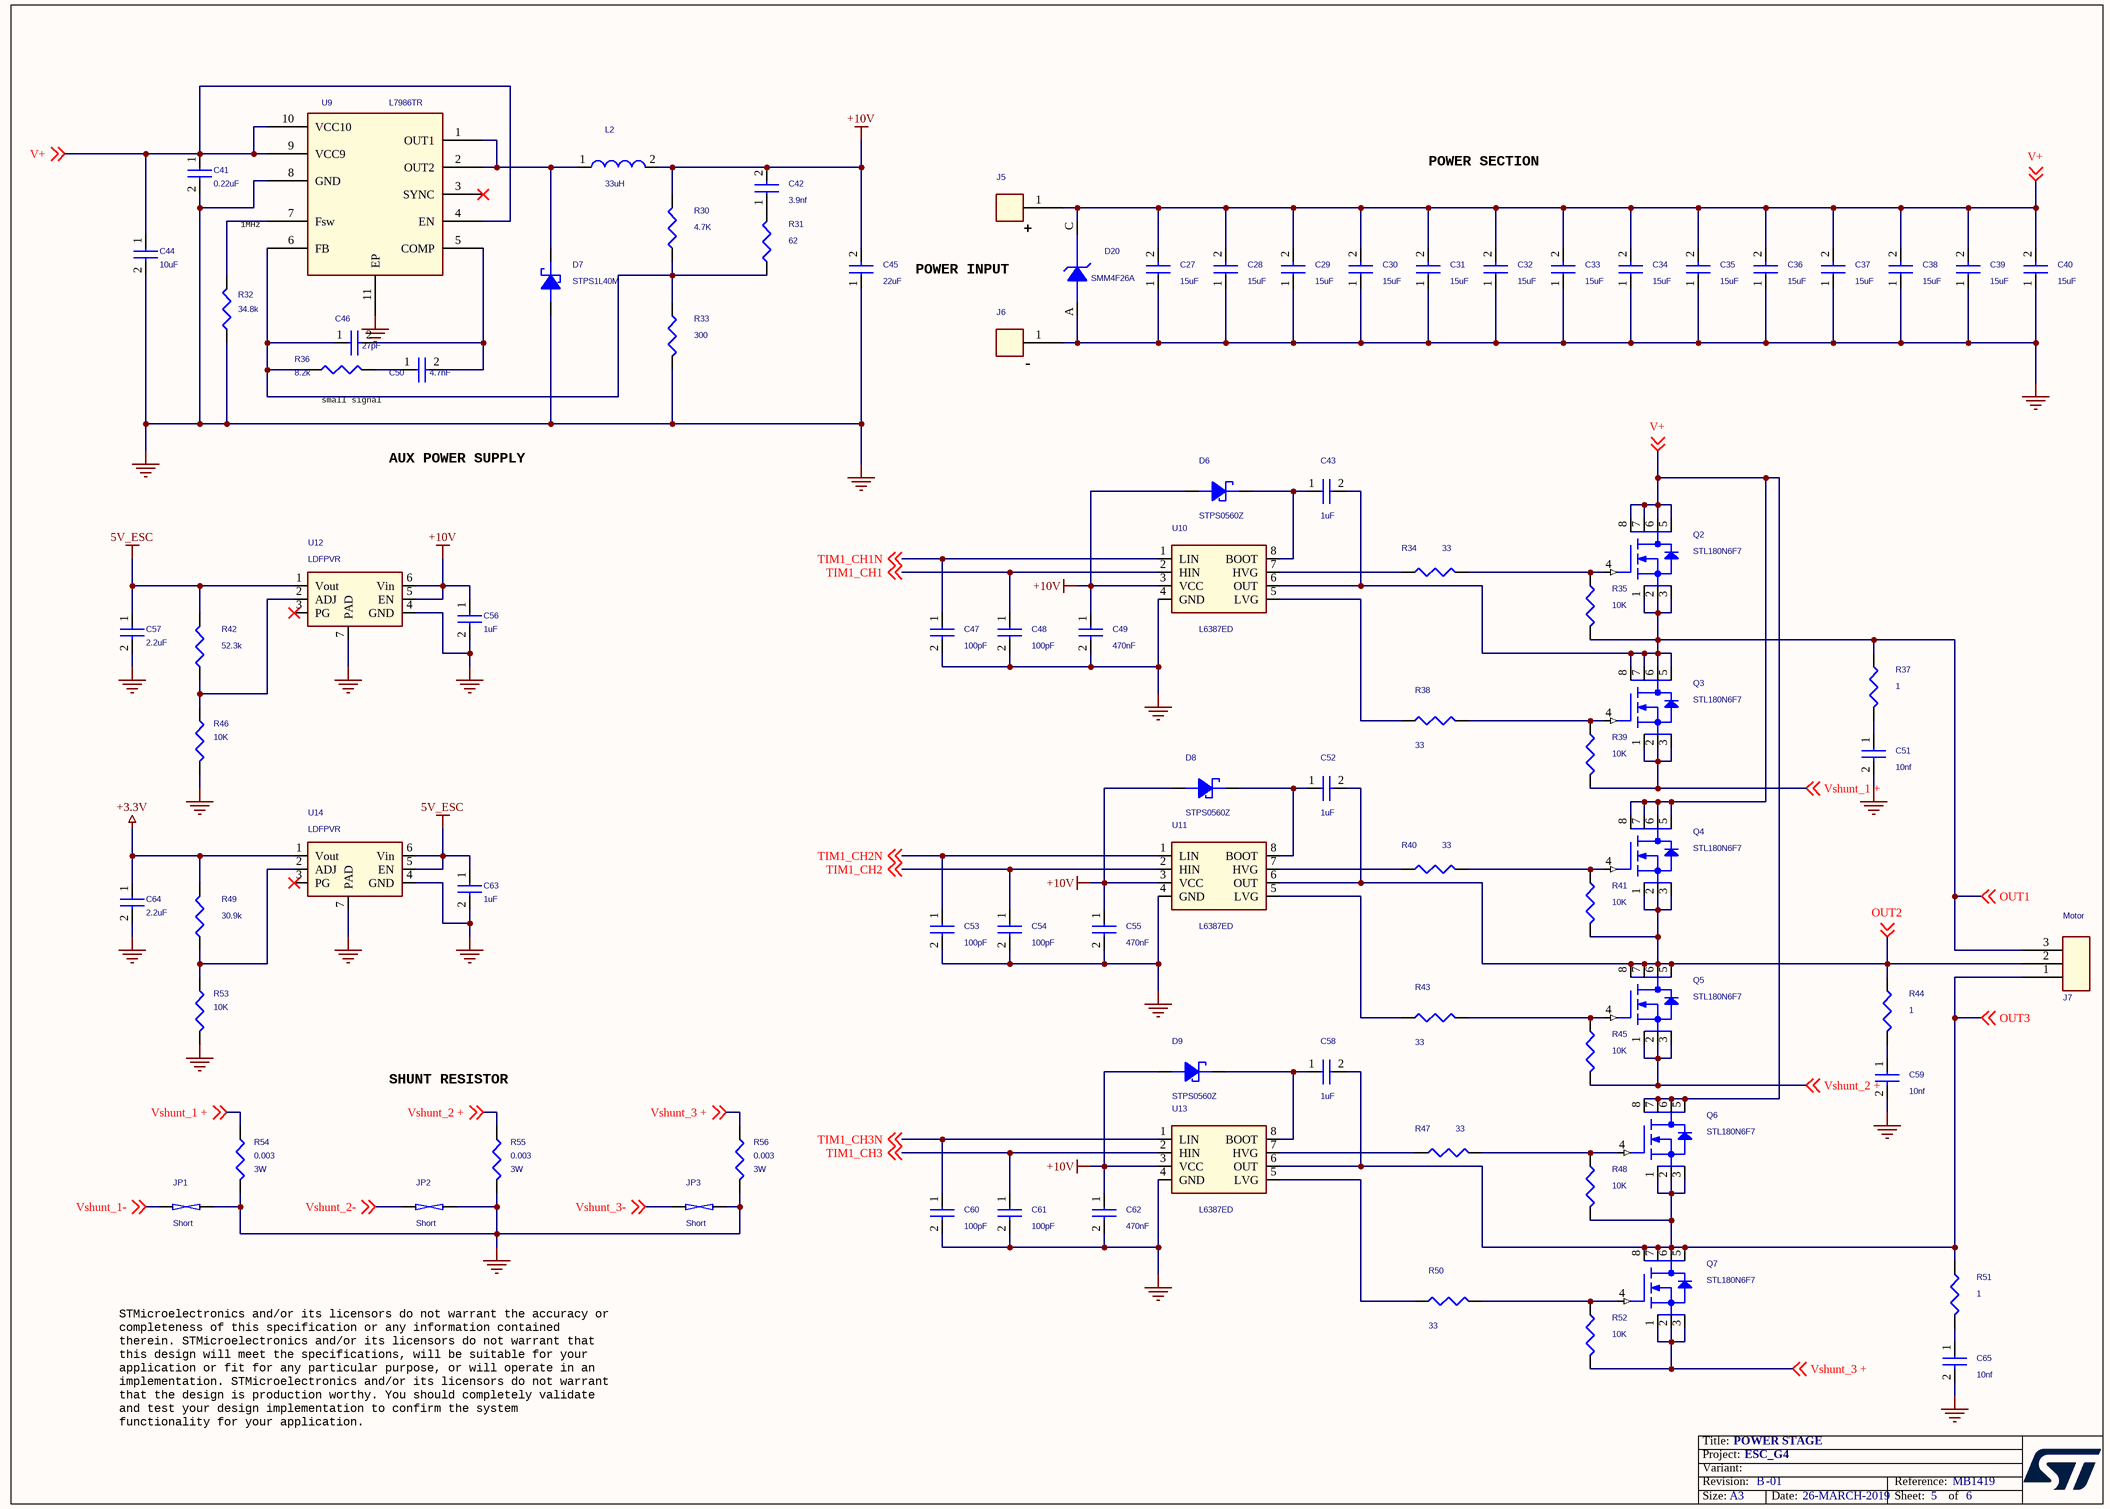
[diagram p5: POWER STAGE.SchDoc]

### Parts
C27  15uF  [C_0805_HD]
C28  15uF  [C_0805_HD]
C29  15uF  [C_0805_HD]
C30  15uF  [C_0805_HD]
C31  15uF  [C_0805_HD]
C32  15uF  [C_0805_HD]
C33  15uF  [C_0805_HD]
C34  15uF  [C_0805_HD]
C35  15uF  [C_0805_HD]
C36  15uF  [C_0805_HD]
C37  15uF  [C_0805_HD]
C38  15uF  [C_0805_HD]
C39  15uF  [C_0805_HD]
C40  15uF  [C_0805_HD]
C41  0.22uF  [C_0603_HD]
C42  3.9nf  [C_0402]
C43  1uF  [C_0603_HD]
C44  10uF  [C_1206]
C45  22uF  [C_1206]
C46  27pF  [C_0402]
C47  100pF  [C_0402]
C48  100pF  [C_0402]
C49  470nF  [C_0603_HD]
C50  4.7nF  [C_0402]
C51  10nf  [C_0603]
C52  1uF  [C_0603_HD]
C53  100pF  [C_0402]
C54  100pF  [C_0402]
C55  470nF  [C_0603_HD]
C56  1uF  [C_0402]
C57  2.2uF  [C_0402]
C58  1uF  [C_0603_HD]
C59  10nf  [C_0603]
C60  100pF  [C_0402]
C61  100pF  [C_0402]
C62  470nF  [C_0603_HD]
C63  1uF  [C_0402]
C64  2.2uF  [C_0402]
C65  10nf  [C_0603]
D6  STPS0560Z  [SOD_123]
D7  STPS1L40M  [do216-aa_stmite]
D8  STPS0560Z  [SOD_123]
D9  STPS0560Z  [SOD_123]
D20  SMM4F26A  [do216-aa-flat]
J5  CON1  [wire1_220s]  (value not drawn)
J6  CON1  [wire1_220s]  (value not drawn)
J7  Motor  [conn_motor_out]
JP1  Short  [SHORT]
JP2  Short  [SHORT]
JP3  Short  [SHORT]
L2  33uH  [ind_Coilcraft-LPS4018]
Q2  STL180N6F7  [power_flat_5x6]
Q3  STL180N6F7  [power_flat_5x6]
Q4  STL180N6F7  [power_flat_5x6]
Q5  STL180N6F7  [power_flat_5x6]
Q6  STL180N6F7  [power_flat_5x6]
Q7  STL180N6F7  [power_flat_5x6]
R30  4.7K  [R_0402]
R31  62  [R_0402]
R32  34.8k  [R_0402]
R33  300  [R_0402]
R34  33  [R_0603_HD]
R35  10K  [R_0402]
R36  8.2k  [R_0402]
R37  1  [R_0805]
R38  33  [R_0603_HD]
R39  10K  [R_0402]
R40  33  [R_0603_HD]
R41  10K  [R_0402]
R42  52.3k  [R_0402]
R43  33  [R_0603_HD]
R44  1  [R_0805]
R45  10K  [R_0402]
R46  10K  [R_0402]
R47  33  [R_0603_HD]
R48  10K  [R_0402]
R49  30.9k  [R_0402]
R50  33  [R_0603_HD]
R51  1  [R_0805]
R52  10K  [R_0402]
R53  10K  [R_0402]
R54  0.003  Rated Power: 3W  [resc635x300x60l193n]
R55  0.003  Rated Power: 3W  [resc635x300x60l193n]
R56  0.003  Rated Power: 3W  [resc635x300x60l193n]
U9  L7986TR  [son11p50_300x300x100l40x24t2-1]
U10  L6387ED  [SOIC8P127_490X600X175L83X42N]
U11  L6387ED  [SOIC8P127_490X600X175L83X42N]
U12  LDFPVR  [son7p65_200x200x100l25x30t18-1]
U13  L6387ED  [SOIC8P127_490X600X175L83X42N]
U14  LDFPVR  [son7p65_200x200x100l25x30t18-1]

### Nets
5V_ESC: C57.1 C63.1 R42.2 U12.1(Vout) U14.5(EN) U14.6(Vin)
+3.3V: C64.1 R49.2 U14.1(Vout)
+10V: C42.2 C45.2 C49.1 C55.1 C56.1 C62.1 D6.A D8.A D9.A L2.2 R30.1 U10.3(VCC) U11.3(VCC) U12.5(EN) U12.6(Vin) U13.3(VCC)
GND: C27.1 C28.1 C29.1 C30.1 C31.1 C32.1 C33.1 C34.1 C35.1 C36.1 C37.1 C38.1 C39.1 C40.1 C41.2 C44.2 C45.1 C47.2 C48.2 C49.2 C51.2 C53.2 C54.2 C55.2 C56.2 C57.2 C59.2 C60.2 C61.2 C62.2 C63.2 C64.2 C65.2 D7.A D20.A J6.1 JP1.2 JP2.2 JP3.2 R32.2 R33.1 R46.2 R53.2 R54.2 R55.2 R56.2 U9.8(GND) U9.11(EP) U10.4(GND) U11.4(GND) U12.4(GND) U12.7(PAD) U13.4(GND) U14.4(GND) U14.7(PAD)
OUT1: C43.2 J7.3 Q2.1(S1) Q2.2(S2) Q2.3(S3) Q3.5(D) Q3.6(D6) Q3.7(D7) Q3.8(D8) R35.2 R37.1 U10.6(OUT) ; off-sheet OUT1
OUT2: C52.2 J7.2 Q4.1(S1) Q4.2(S2) Q4.3(S3) Q5.5(D) Q5.6(D6) Q5.7(D7) Q5.8(D8) R41.2 R44.1 U11.6(OUT) ; off-sheet OUT2
OUT3: C58.2 J7.1 Q6.1(S1) Q6.2(S2) Q6.3(S3) Q7.5(D) Q7.6(D6) Q7.7(D7) Q7.8(D8) R48.2 R51.1 U13.6(OUT) ; off-sheet OUT3
TIM1_CH1: C48.1 U10.2(HIN) ; off-sheet TIM1_CH1  [project net UH]
TIM1_CH1N: C47.1 U10.1(LIN) ; off-sheet TIM1_CH1N  [project net PC13-UL]
TIM1_CH2: C54.1 U11.2(HIN) ; off-sheet TIM1_CH2  [project net VH]
TIM1_CH2N: C53.1 U11.1(LIN) ; off-sheet TIM1_CH2N  [project net VL]
TIM1_CH3: C61.1 U13.2(HIN) ; off-sheet TIM1_CH3  [project net WH]
TIM1_CH3N: C60.1 U13.1(LIN) ; off-sheet TIM1_CH3N  [project net WL]
V+: C27.2 C28.2 C29.2 C30.2 C31.2 C32.2 C33.2 C34.2 C35.2 C36.2 C37.2 C38.2 C39.2 C40.2 C41.1 C44.1 D20.C J5.1 Q2.5(D) Q2.6(D6) Q2.7(D7) Q2.8(D8) Q4.5(D) Q4.6(D6) Q4.7(D7) Q4.8(D8) Q6.5(D) Q6.6(D6) Q6.7(D7) Q6.8(D8) U9.4(EN) U9.9(VCC9) U9.10(VCC10) ; off-sheet V+
Vshunt_1 +: Q3.1(S1) Q3.2(S2) Q3.3(S3) R39.2 R54.1 ; off-sheet Vshunt_1 +
Vshunt_1-: JP1.1 ; off-sheet Vshunt_1-  [project net Curr_fdbk1_OPAmp-]
Vshunt_2 +: Q5.1(S1) Q5.2(S2) Q5.3(S3) R45.2 R55.1 ; off-sheet Vshunt_2 +
Vshunt_2-: JP2.1 ; off-sheet Vshunt_2-  [project net Curr_fdbk2_OPAmp-]
Vshunt_3 +: Q7.1(S1) Q7.2(S2) Q7.3(S3) R52.2 R56.1 ; off-sheet Vshunt_3 +
Vshunt_3-: JP3.1 ; off-sheet Vshunt_3-  [project net Curr_fdbk3_OPAmp-]
NetC42_1: C42.1 R31.1
NetC43_1: C43.1 D6.C U10.8(BOOT)
NetC46_1: C46.1 R30.2 R31.2 R33.2 R36.2 U9.6(FB)
NetC46_2: C46.2 C50.2 U9.5(COMP)
NetC50_1: C50.1 R36.1
NetC51_1: C51.1 R37.2
NetC52_1: C52.1 D8.C U11.8(BOOT)
NetC58_1: C58.1 D9.C U13.8(BOOT)
NetC59_1: C59.1 R44.2
NetC65_1: C65.1 R51.2
NetD7_C: D7.C L2.1 U9.1(OUT1) U9.2(OUT2)
NetQ2_4: Q2.4(G) R34.2 R35.1
NetQ3_4: Q3.4(G) R38.2 R39.1
NetQ4_4: Q4.4(G) R40.2 R41.1
NetQ5_4: Q5.4(G) R43.2 R45.1
NetQ6_4: Q6.4(G) R47.2 R48.1
NetQ7_4: Q7.4(G) R50.2 R52.1
NetR32_1: R32.1 U9.7(Fsw)
NetR34_1: R34.1 U10.7(HVG)
NetR38_1: R38.1 U10.5(LVG)
NetR40_1: R40.1 U11.7(HVG)
NetR42_1: R42.1 R46.1 U12.2(ADJ)
NetR43_1: R43.1 U11.5(LVG)
NetR47_1: R47.1 U13.7(HVG)
NetR49_1: R49.1 R53.1 U14.2(ADJ)
NetR50_1: R50.1 U13.5(LVG)

Not connected (* = marked no-connect by the designer): U9 3(SYNC)*; U12 3(PG)*; U14 3(PG)*

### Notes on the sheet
- POWER SECTION
- 1MHz
- (near J5) +
- POWER INPUT
- (near J6) -
- (near R36) small signal
- AUX POWER SUPPLY
- (near R55) SHUNT RESISTOR
- STMicroelectronics and/or its licensors do not warrant the accuracy or
  completeness of this specification or any information contained
  therein. STMicroelectronics and/or its licensors do not warrant that
  this design will meet the specifications, will be suitable for your
  application or fit for any particular purpose, or will operate in an
  implementation. STMicroelectronics and/or its licensors do not warrant
  that the design is production worthy. You should completely validate
  and test your design implementation to confirm the system
  functionality for your application.

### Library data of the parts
C27-C40 = CAP_Dup1: CAP CER 15UF 35V X5R 0805; PART_NUMBER: TMP-773; Manufacturer: TDK Corporation; Manufacturer PN: C2012X5R1V156M125AC; Dielectric Type: Capacitors; Tolerance: 20%; CLASS: DISCRETE
C41 = CAP_Dup1: CAP CER 0.22UF 50V X7R 0603; Manufacturer PN: CGA3E3X7R1H224K080AD; Manufacturer: TDK Corporation; PART_NUMBER: TMP-138; CLASS: DISCRETE; Tolerance: 10%; Dielectric Type: Capacitors
C42 = CAP_Dup1: CAP CER 3900PF 16V X7R 0402; Manufacturer PN: C0402C392K4RAC7867; Manufacturer: KEMET; PART_NUMBER: TMP-419; CLASS: DISCRETE; Tolerance: 10%; Dielectric Type: Capacitors
C43 C52 C58 = CAP_Dup1: CAP CER 1UF 25V X7R 0603; PART_NUMBER: TMP-446; Manufacturer: Wurth Electronics Inc.; Manufacturer PN: 885012206076; Dielectric Type: Capacitors; Tolerance: 10%; CLASS: DISCRETE
C44 = CAP_Dup1: CAP CER 10UF 50V X7R 1206; Manufacturer PN: CL31B106KBHNNNE; Manufacturer: Samsung Electro-Mechanics America, Inc.; PART_NUMBER: CAP-00000016; CLASS: DISCRETE; Tolerance: 10%; Dielectric Type: Capacitors
C45 = CAP_Dup1: CAP CER 22UF 25V X5R 1206; Manufacturer PN: GRT31CR61E226ME01L; Manufacturer: Murata Electronics North America; PART_NUMBER: TMP-421; CLASS: DISCRETE; Tolerance: 20%; Dielectric Type: Capacitors
C46 = CAP_Dup1: CAP CER 27PF 25V C0G/NP0 0402; Manufacturer PN: GRM1555C1E270JA01D; Manufacturer: Murata Electronics North America; PART_NUMBER: TMP-416; CLASS: DISCRETE; Tolerance: 5%; Temperature Coefficient: C0G, NP0; Dielectric Type: Capacitors
C47 C48 C53 C54 C60 C61 = CAP_Dup1: CAP CER 100PF 25V X7R 0402; PART_NUMBER: TMP-426; Manufacturer: Wurth Electronics Inc.; Manufacturer PN: 885012205038; Dielectric Type: Capacitors; Tolerance: 10%; CLASS: DISCRETE
C49 C55 C62 = CAP_Dup1: CAP CER 0.47UF 25V X7R 0603; PART_NUMBER: TMP-428; Manufacturer: Wurth Electronics Inc.; Manufacturer PN: 885012206075; Dielectric Type: Capacitors; Tolerance: 10%; CLASS: DISCRETE
C50 = CAP_Dup1: CAP CER 4700PF 16V X7R 0402; Manufacturer PN: 885012205029; Manufacturer: Wurth Electronics Inc.; PART_NUMBER: TMP-417; CLASS: DISCRETE; Tolerance: 10%; Dielectric Type: Capacitors
C51 C59 C65 = CAP_Dup1: CAP CER 10000PF 100V X7R 0603; PART_NUMBER: CAP-00000040; Manufacturer: TDK Corporation; Manufacturer PN: C1608X7R2A103M080AA; Dielectric Type: Capacitors; Tolerance: 20%; CLASS: DISCRETE
C56 C63 = CAP_Dup1: CAP CER 1UF 25V X5R 0402; Manufacturer PN: GRM155R61E105KA12D; Manufacturer: Murata Electronics North America; PART_NUMBER: CAP-00000006; CLASS: DISCRETE; Tolerance: 10%; Dielectric Type: Capacitors
C57 C64 = CAP_Dup1: CAP CER 2.2UF 10V X5R 0402; PART_NUMBER: TMP-449; Manufacturer: Wurth Electronics Inc.; Manufacturer PN: 885012105013; Dielectric Type: Capacitors; Tolerance: 20%; CLASS: DISCRETE
D6 D8 D9 = DIODE_SCHOTTKY_0: DIODE SCHOTTKY 60V 500MA SOD123; Manufacturer: STMicroelectronics; PART_NUMBER: TMP-373; CLASS: DISCRETE; Rated Voltage: 530mV @ 500mA
D7 = DIODE_SCHOTTKY_0: DIODE SCHOTTKY 40V 1A STMITE; PART_NUMBER: TMP-372; Manufacturer: STMicroelectronics; Rated Voltage: 460mV @ 1A; CLASS: DISCRETE
D20 = DIODE_TRANSIL_UNI_0: TVS DIODE 26VWM 53.5VC DO222AA; Manufacturer PN: SMM4F26A-TR; Manufacturer: STMicroelectronics; PART_NUMBER: TMP-376; CLASS: DISCRETE
J5 J6 = CON1: SOLDER PADS
J7 = CON3: SOLDER PADS
JP1-JP3 = SHORT: 2 PIN SHORTED TO CONNECT DIFFERENT NETS; PART_NUMBER: TMP-442; CLASS: DISCRETE
L2 = IND: Fixed Inductors LPS4018 Low Profile 33uH 0.8A 20% SMD; Manufacturer PN: LPS4018-333MRB; Manufacturer: Coilcraft; PART_NUMBER: TMP-377; CLASS: DISCRETE
Q2-Q7 = MOSFET_N_DIODE_SSSGDDDD: N-channel 60 V, 1.9 mO typ., 120 A STripFET™ F7; PART_NUMBER: TMP-772; Manufacturer: STMicroelectronics; CLASS: DISCRETE; Rated Voltage: 60V
R30 = RES: RES SMD 4.7K OHM 1% 1/16W 0402; Manufacturer PN: CRG0402F4K7; Manufacturer: TE Connectivity Passive Product; PART_NUMBER: TMP-403; CLASS: DISCRETE; Rated Power: 0.063W, 1/16W; Temperature Coefficient: 100ppm/C
R31 = RES: RES SMD 62 OHM 1% 1/16W 0402; Manufacturer PN: RC0402FR-0762RL; Manufacturer: Yageo; PART_NUMBER: TMP-420; CLASS: DISCRETE; Rated Power: 0.063W, 1/16W; Temperature Coefficient: 100ppm/C
R32 = RES: RES SMD 34.8K OHM 1% 1/16W 0402; Manufacturer PN: RC0402FR-0734K8L; Manufacturer: Yageo; PART_NUMBER: TMP-415; CLASS: DISCRETE; Rated Power: 0.063W, 1/16W; Temperature Coefficient: 100ppm/C
R33 = RES: RES SMD 300 OHM 1% 1/16W 0402; PART_NUMBER: TMP-418; Manufacturer: Yageo; Manufacturer PN: RC0402FR-07300RL; Temperature Coefficient: 100ppm/C; Rated Power: 0.063W, 1/16W; CLASS: DISCRETE
R34 R40 = RES: RES SMD 33 OHM 1% 1/10W 0603; Manufacturer PN: 9C06031A33R0FKHFT; Manufacturer: Yageo; PART_NUMBER: TMP-266; CLASS: DISCRETE; Rated Power: 0.1W, 1/10W; Temperature Coefficient: 100ppm/C
R35 R39 R41 R45 = RES: as R3 on sheet DAUGHTERBOARD
R36 = RES: RES SMD 8.2K OHM 5% 1/16W 0402; Manufacturer PN: RC0402JR-078K2L; Manufacturer: Yageo; PART_NUMBER: RES-00000047; CLASS: DISCRETE; Rated Power: 0.063W, 1/16W; Temperature Coefficient: 100ppm/C
R37 R44 R51 = RES: RES SMD 1 OHM 5% 1/8W 0805; PART_NUMBER: TMP-430; Manufacturer: Panasonic Electronic Components; Manufacturer PN: ERJ-6GEYJ1R0V; Temperature Coefficient: -100/ +600ppm/C; Rated Power: 0.125W, 1/8W; CLASS: DISCRETE
R38 R43 R47 R50 = RES: RES SMD 33 OHM 1% 1/10W 0603; PART_NUMBER: TMP-266; Manufacturer: Yageo; Manufacturer PN: 9C06031A33R0FKHFT; Temperature Coefficient: 100ppm/C; Rated Power: 0.1W, 1/10W; CLASS: DISCRETE
R42 = RES: RES SMD 52.3K OHM 1% 1/16W 0402; Manufacturer PN: RC1005F5232CS; Manufacturer: Samsung Electro-Mechanics; PART_NUMBER: TMP-447; CLASS: DISCRETE; Rated Power: 0.063W, 1/16W; Temperature Coefficient: 100ppm/C
R46 = RES: RES SMD 10K OHM 1% 1/16W 0402; PART_NUMBER: TMP-396; Manufacturer: Yageo; Manufacturer PN: RC0402FR-0710KL; CLASS: DISCRETE; Rated Power: 0.063W, 1/16W; Temperature Coefficient: 100ppm/C
R48 R52 R53 = RES: as R10 on sheet DAUGHTERBOARD
R49 = RES: RES SMD 30.9K OHM 1% 1/10W 0402; PART_NUMBER: TMP-448; Manufacturer: Panasonic Electronic Components; Manufacturer PN: ERJ-2RKF3092X; Temperature Coefficient: 100ppm/C; Rated Power: 0.1W, 1/10W; CLASS: DISCRETE
R54 R56 = RES: RES 0.003 OHM 1% 3W 2512; PART_NUMBER: TMP-766; Manufacturer: TE Connectivity Passive Product; Manufacturer PN: TLR3A30DR003FTDG; Temperature Coefficient: 50ppm/C; CLASS: DISCRETE
R55 = RES: RES 0.003 OHM 1% 3W 2512; Manufacturer PN: TLR3A30DR003FTDG; Manufacturer: TE Connectivity Passive Product; PART_NUMBER: TMP-766; CLASS: DISCRETE; Temperature Coefficient: 50ppm/C
U9 = L7986TR: IC REG BUCK ADJ 3A 10VDFPN; Manufacturer: STMicroelectronics; PART_NUMBER: TMP-362
U10 = L6387E: IC DRIVER HI/LO SIDE HV 8-SOIC; Manufacturer: STMicroelectronics; PART_NUMBER: TMP-367; Supply Voltage: 17V (Max)
U11 U13 = L6387E: IC DRIVER HI/LO SIDE HV 8-SOIC; PART_NUMBER: TMP-367; Manufacturer: STMicroelectronics; Supply Voltage: 17V (Max)
U12 = LDFPxR: IC REG LINEAR POS ADJ 1A 6DFN; PART_NUMBER: TMP-450; Manufacturer: STMicroelectronics
U14 = LDFPxR: IC REG LINEAR POS ADJ 1A 6DFN; Manufacturer: STMicroelectronics; PART_NUMBER: TMP-450

## Sheet SENSING.SchDoc: SENSING
size A3; DocumentNumber: 6; SheetNumber: 6; SheetTotal: 6
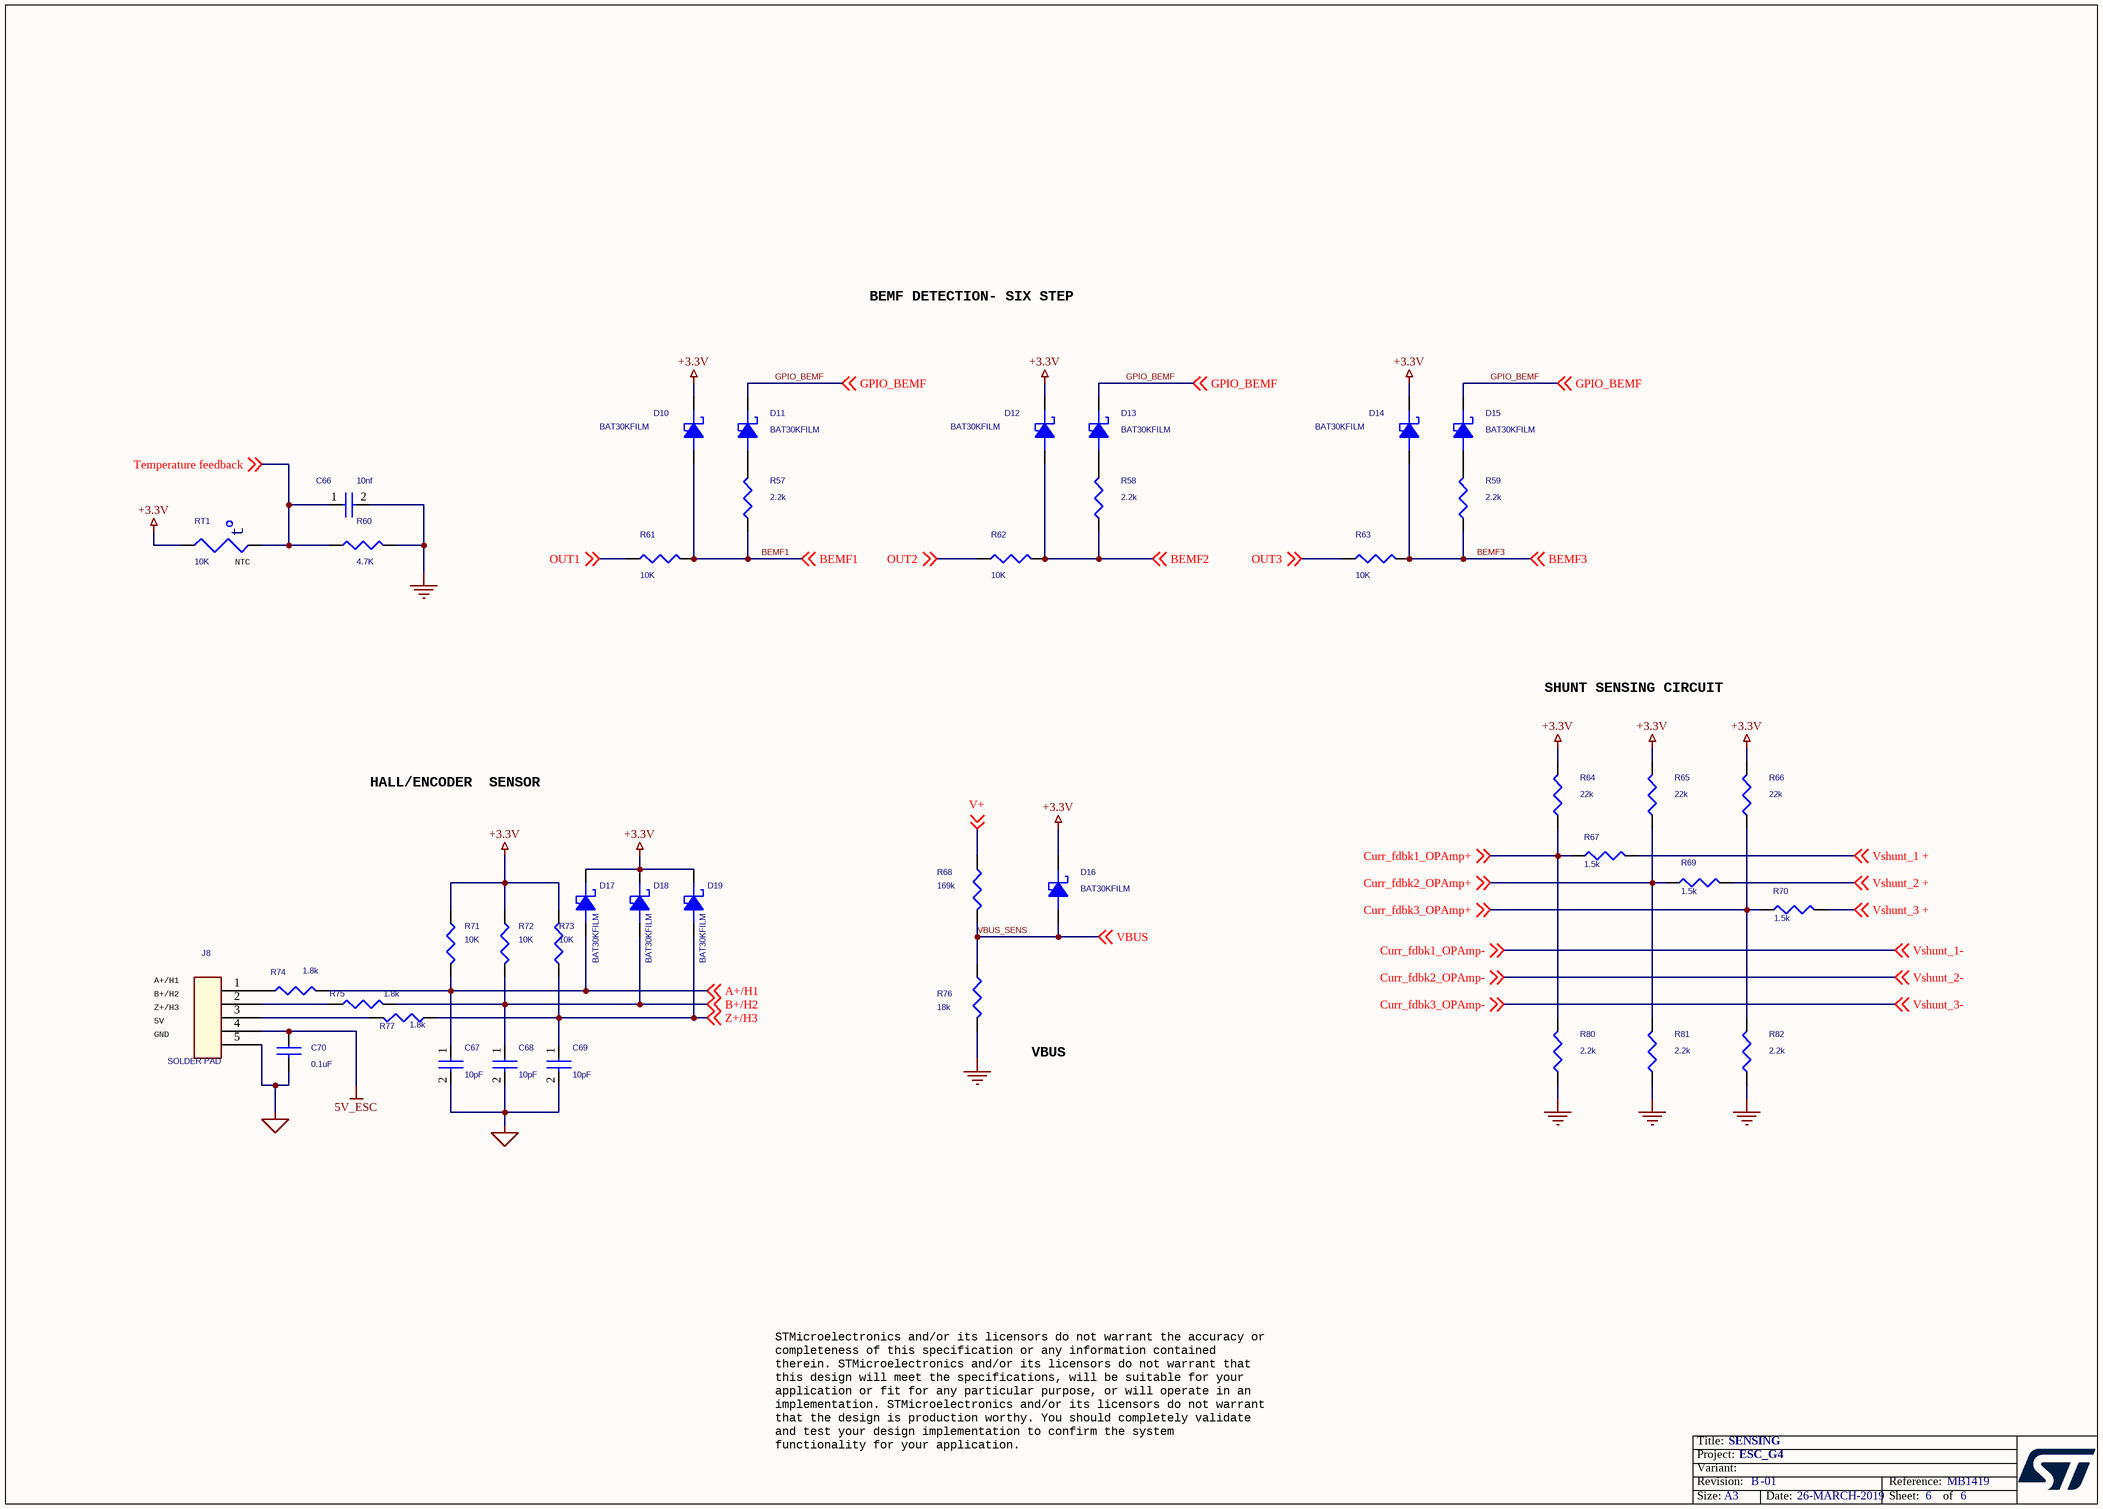
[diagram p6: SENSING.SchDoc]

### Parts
C66  10nf  [C_0402]
C67  10pF  [C_0402]
C68  10pF  [C_0402]
C69  10pF  [C_0402]
C70  0.1uF  [C_0402]
D10  BAT30KFILM  [sodfl160x80x65l30x30n]
D11  BAT30KFILM  [sodfl160x80x65l30x30n]
D12  BAT30KFILM  [sodfl160x80x65l30x30n]
D13  BAT30KFILM  [sodfl160x80x65l30x30n]
D14  BAT30KFILM  [sodfl160x80x65l30x30n]
D15  BAT30KFILM  [sodfl160x80x65l30x30n]
D16  BAT30KFILM  [sodfl160x80x65l30x30n]
D17  BAT30KFILM  [sodfl160x80x65l30x30n]
D18  BAT30KFILM  [sodfl160x80x65l30x30n]
D19  BAT30KFILM  [sodfl160x80x65l30x30n]
J8  SOLDER PAD  [SOLDER_PAD_5PIN_SMD]
R57  2.2k  [R_0402]
R58  2.2k  [R_0402]
R59  2.2k  [R_0402]
R60  4.7K  [R_0402]
R61  10K  [R_0603_HD]
R62  10K  [R_0603_HD]
R63  10K  [R_0603]
R64  22k  [r_0402]
R65  22k  [r_0402]
R66  22k  [r_0402]
R67  1.5k  [R_0402]
R68  169k  [R_0402]
R69  1.5k  [R_0402]
R70  1.5k  [R_0402]
R71  10K  [R_0402]
R72  10K  [R_0402]
R73  10K  [R_0402]
R74  1.8k  [R_0402]
R75  1.8k  [R_0402]
R76  18k  [R_0402]
R77  1.8k  [R_0402]
R80  2.2k  [R_0402]
R81  2.2k  [R_0402]
R82  2.2k  [R_0402]
RT1  10K  [R_0402]

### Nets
5V_ESC: C70.1 J8.4
+3.3V: D10.C D12.C D14.C D16.C D17.C D18.C D19.C R64.2 R65.2 R66.2 R71.1 R72.1 R73.2 RT1.1
GND: C66.2 C67.2 C68.2 C69.2 C70.2 J8.5 R60.2 R76.2 R80.1 R81.1 R82.1  [also labelled GND_SIGNAL]
A+/H1: C67.1 D17.A R71.2 R74.2 ; off-sheet A+/H1
B+/H2: C68.1 D18.A R72.2 R75.2 ; off-sheet B+/H2
BEMF1: D10.A R57.1 R61.2 ; off-sheet BEMF1
BEMF2: D12.A R58.1 R62.2 ; off-sheet BEMF2
BEMF3: D14.A R59.1 R63.2 ; off-sheet BEMF3
Curr_fdbk1_OPAmp+: R64.1 R67.1 R80.2 ; off-sheet Curr_fdbk1_OPAmp+
Curr_fdbk1_OPAmp-: off-sheet Curr_fdbk1_OPAmp-, off-sheet Vshunt_1-  [also labelled Vshunt_1-]
Curr_fdbk2_OPAmp+: R65.1 R69.1 R81.2 ; off-sheet Curr_fdbk2_OPAmp+
Curr_fdbk2_OPAmp-: off-sheet Curr_fdbk2_OPAmp-, off-sheet Vshunt_2-  [also labelled Vshunt_2-]
Curr_fdbk3_OPAmp+: R66.1 R70.1 R82.2 ; off-sheet Curr_fdbk3_OPAmp+
Curr_fdbk3_OPAmp-: off-sheet Curr_fdbk3_OPAmp-, off-sheet Vshunt_3-  [also labelled Vshunt_3-]
GPIO_BEMF: D11.C D13.C D15.C ; off-sheet GPIO_BEMF
OUT1: R61.1 ; off-sheet OUT1
OUT2: R62.1 ; off-sheet OUT2
OUT3: R63.1 ; off-sheet OUT3
Temperature feedback: C66.1 R60.1 RT1.2 ; off-sheet Temperature feedback
V+: R68.1 ; off-sheet V+
VBUS: D16.A R68.2 R76.1 ; off-sheet VBUS  [also labelled VBUS_SENS]  [project net PA0 - BUSV]
Vshunt_1 +: R67.2 ; off-sheet Vshunt_1 +
Vshunt_2 +: R69.2 ; off-sheet Vshunt_2 +
Vshunt_3 +: R70.2 ; off-sheet Vshunt_3 +
Z+/H3: C69.1 D19.A R73.1 R77.1 ; off-sheet Z+/H3
NetD11_A: D11.A R57.2
NetD13_A: D13.A R58.2
NetD15_A: D15.A R59.2
NetJ8_1: J8.1 R74.1
NetJ8_2: J8.2 R75.1
NetJ8_3: J8.3 R77.2

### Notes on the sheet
- BEMF DETECTION- SIX STEP
- (near RT1) NTC
- SHUNT SENSING CIRCUIT
- HALL/ENCODER  SENSOR
- (near J8) A+/H1
- 5V
- (near J8) Z+/H3
- (near J8) B+/H2
- GND
- VBUS
- STMicroelectronics and/or its licensors do not warrant the accuracy or
  completeness of this specification or any information contained
  therein. STMicroelectronics and/or its licensors do not warrant that
  this design will meet the specifications, will be suitable for your
  application or fit for any particular purpose, or will operate in an
  implementation. STMicroelectronics and/or its licensors do not warrant
  that the design is production worthy. You should completely validate
  and test your design implementation to confirm the system
  functionality for your application.

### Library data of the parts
C66 = CAP_Dup1: CAP CER 10000PF 10V X7R 0402; PART_NUMBER: CAP-00000003; Manufacturer: Wurth Electronics Inc.; Manufacturer PN: 885012205012; Dielectric Type: Capacitors; Tolerance: 10%; CLASS: DISCRETE
C67-C69 = CAP: CAP CER 10PF 10V C0G/NP0 0402; Manufacturer PN: 885012005007; Manufacturer: Wurth Electronics Inc.; PART_NUMBER: TMP-395; CLASS: DISCRETE; Tolerance: 5%; Temperature Coefficient: C0G, NP0; Dielectric Type: Capacitors
C70 = CAP_4: CAP CER 0.1UF 16V X7R 0402; Manufacturer PN: 885012205037; Manufacturer: Wurth Electronics Inc.; PART_NUMBER: CAP-00000053; CLASS: DISCRETE; Tolerance: 10%; Dielectric Type: Capacitors
D10 D17 D19 = DIODE_SCHOTTKY_0: DIODE SCHOTTKY 30V 300MA SOD523; Manufacturer: STMicroelectronics; PART_NUMBER: TMP-46; CLASS: DISCRETE; Rated Voltage: 530mV @ 300mA
D11-D16 D18 = DIODE_SCHOTTKY_0: DIODE SCHOTTKY 30V 300MA SOD523; PART_NUMBER: TMP-46; Manufacturer: STMicroelectronics; Rated Voltage: 530mV @ 300mA; CLASS: DISCRETE
J8 = CON5: SOLDER PADS
R57-R59 = RES: RES SMD 2.2K OHM 1% 1/16W 0402; Manufacturer PN: RC0402FR-072K2L; Manufacturer: Yageo; PART_NUMBER: TMP-444; CLASS: DISCRETE; Rated Power: 0.063W, 1/16W; Temperature Coefficient: 100ppm/C
R60 = RES: as R19 on sheet DAUGHTERBOARD
R61 R62 = RES: RES SMD 10K OHM 1% 1/10W 0603; PART_NUMBER: RES-00000015; Manufacturer: Yageo; Manufacturer PN: RC0603FR-0710KL; Temperature Coefficient: 100ppm/C; Rated Power: 0.1W, 1/10W; CLASS: DISCRETE
R63 = RES: RES SMD 10K OHM 1% 1/10W 0603; PART_NUMBER: RES-00000015; Manufacturer: Yageo; Manufacturer PN: RC0603FR-0710KL; ALT_SYMBOLS: r_0603_hd; Temperature Coefficient: 100ppm/C; Rated Power: 0.1W, 1/10W; CLASS: DISCRETE
R64-R66 = RES: RES SMD 22K OHM 1% 1/10W 0402; PART_NUMBER: TMP-751; Manufacturer: Panasonic Electronic Components; Manufacturer PN: ERJ-2RKF2202X; Temperature Coefficient: 100ppm/C; Rated Power: 0.1W, 1/10W; CLASS: DISCRETE
R67 R69 R70 = RES: as R5 on sheet DAUGHTERBOARD
R68 = RES: RES SMD 169K OHM 1% 1/16W 0402; PART_NUMBER: TMP-424; Manufacturer: Yageo; Manufacturer PN: RC0402FR-07169KL; Temperature Coefficient: 100ppm/C; Rated Power: 0.063W, 1/16W; CLASS: DISCRETE
R71 = RES: as R10 on sheet DAUGHTERBOARD
R72 R73 = RES: as R3 on sheet DAUGHTERBOARD
R74 = RES: RES SMD 1.8K OHM 1% 1/16W 0402; Manufacturer PN: RC0402FR-071K8L; Manufacturer: Yageo; PART_NUMBER: TMP-394; CLASS: DISCRETE; Rated Power: 0.063W, 1/16W; Temperature Coefficient: 100ppm/C
R75 R77 = RES: RES SMD 1.8K OHM 1% 1/16W 0402; PART_NUMBER: TMP-394; Manufacturer: Yageo; Manufacturer PN: RC0402FR-071K8L; Temperature Coefficient: 100ppm/C; Rated Power: 0.063W, 1/16W; CLASS: DISCRETE
R76 = RES: RES SMD 18K OHM 1% 1/16W 0402; PART_NUMBER: TMP-425; Manufacturer: Yageo; Manufacturer PN: RC0402FR-0718KL; Temperature Coefficient: 100ppm/C; Rated Power: 0.063W, 1/16W; CLASS: DISCRETE
R80-R82 = RES: RES SMD 2.2K OHM 1% 1/16W 0402; PART_NUMBER: TMP-444; Manufacturer: Yageo; Manufacturer PN: RC0402FR-072K2L; Temperature Coefficient: 100ppm/C; Rated Power: 0.063W, 1/16W; CLASS: DISCRETE
RT1 = NTC: NTC THERMISTOR 10K OHM 1% 0402; Manufacturer PN: NTCG103JF103FT1; Manufacturer: TDK Corporation; PART_NUMBER: TMP-423; CLASS: DISCRETE

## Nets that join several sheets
5V_ESC: CAN (D1.C), DAUGHTERBOARD (C9.1 U5.6 U5.7), POWER STAGE (6 pins), SENSING (C70.1 J8.4)
+3.3V: CAN (C1.1 C2.1 U1.2 U2.3), MCU (11 pins), POWER STAGE (C64.1 R49.2 U14.1), SENSING (14 pins)
+5V: DAUGHTERBOARD (C6.1 U3.2 U3.4), MCU (J3.1)
+10V: DAUGHTERBOARD (C5.1 U3.3), POWER STAGE (16 pins)
GND: CAN (6 pins), DAUGHTERBOARD (43 pins), MCU (15 pins), POWER STAGE (55 pins), SENSING (11 pins)
A+/H1: MCU (U8.44), SENSING (C67.1 D17.A R71.2 R74.2)
B+/H2: MCU (U8.45), SENSING (C68.1 D18.A R72.2 R75.2)
BEMF1: MCU (U8.12), SENSING (D10.A R57.1 R61.2)
BEMF2: MCU (U8.17), SENSING (D12.A R58.1 R62.2)
BEMF3: MCU (U8.24), SENSING (D14.A R59.1 R63.2)
BUTTON: DAUGHTERBOARD (C8.1 R10.2 SW1.3 SW1.4), MCU (U8.39)
CAN_RX: CAN (U2.4), MCU (U8.33)
CAN_SHDN: CAN (U2.5), MCU (TP2.1 U8.40)
CAN_TERM: CAN (U1.3), MCU (R26.2)
CAN_TX: CAN (U2.1), MCU (U8.47)
Curr_fdbk1_OPAmp+: MCU (U8.9), SENSING (R64.1 R67.1 R80.2)
Curr_fdbk1_OPAmp-: MCU (U8.11), POWER STAGE (JP1.1)
Curr_fdbk2_OPAmp+: MCU (U8.15), SENSING (R65.1 R69.1 R81.2)
Curr_fdbk2_OPAmp-: MCU (U8.13), POWER STAGE (JP2.1)
Curr_fdbk3_OPAmp+: MCU (U8.16), SENSING (R66.1 R70.1 R82.2)
Curr_fdbk3_OPAmp-: MCU (U8.19), POWER STAGE (JP3.1)
GPIO_BEMF: MCU (U8.43), SENSING (D11.C D13.C D15.C)
OUT1: POWER STAGE (12 pins), SENSING (R61.1)
OUT2: POWER STAGE (12 pins), SENSING (R62.1)
OUT3: POWER STAGE (12 pins), SENSING (R63.1)
PA0 - BUSV: MCU (C23.1 U8.8), SENSING (D16.A R68.2 R76.1)
PC13-UL: MCU (U8.2), POWER STAGE (C47.1 U10.1)
SPEED: DAUGHTERBOARD (R2.2), MCU (C22.1 U8.25)
T_JTCK: DAUGHTERBOARD (U6.15 U6.26), MCU (J4.2 U8.37)
T_JTMS: DAUGHTERBOARD (R20.2 U6.27), MCU (J4.1 U8.36)
T_NRST: DAUGHTERBOARD (U6.18), MCU (C21.1 U8.7)
Temperature feedback: MCU (U8.27), SENSING (C66.1 R60.1 RT1.2)
UH: MCU (U8.30), POWER STAGE (C48.1 U10.2)
USART2_RX: DAUGHTERBOARD (R23.1), MCU (J3.3 U8.42)
USART2_RX_ST_LINK: DAUGHTERBOARD (R24.1), MCU (J3.2 U8.41)
V+: POWER STAGE (33 pins), SENSING (R68.1)
VH: MCU (U8.31), POWER STAGE (C54.1 U11.2)
VL: MCU (U8.34), POWER STAGE (C53.1 U11.1)
Vshunt_1 +: POWER STAGE (5 pins), SENSING (R67.2)
Vshunt_2 +: POWER STAGE (5 pins), SENSING (R69.2)
Vshunt_3 +: POWER STAGE (5 pins), SENSING (R70.2)
WH: MCU (U8.32), POWER STAGE (C61.1 U13.2)
WL: MCU (U8.28), POWER STAGE (C60.1 U13.1)
Z+/H3: MCU (U8.46), SENSING (C69.1 D19.A R73.1 R77.1)

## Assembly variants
G431CBU6: not fitted C12 J1 J2 J3 J4 J5 J6 J7 J8 JP1 JP2 JP3 R17 TP1 TP2 TP3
